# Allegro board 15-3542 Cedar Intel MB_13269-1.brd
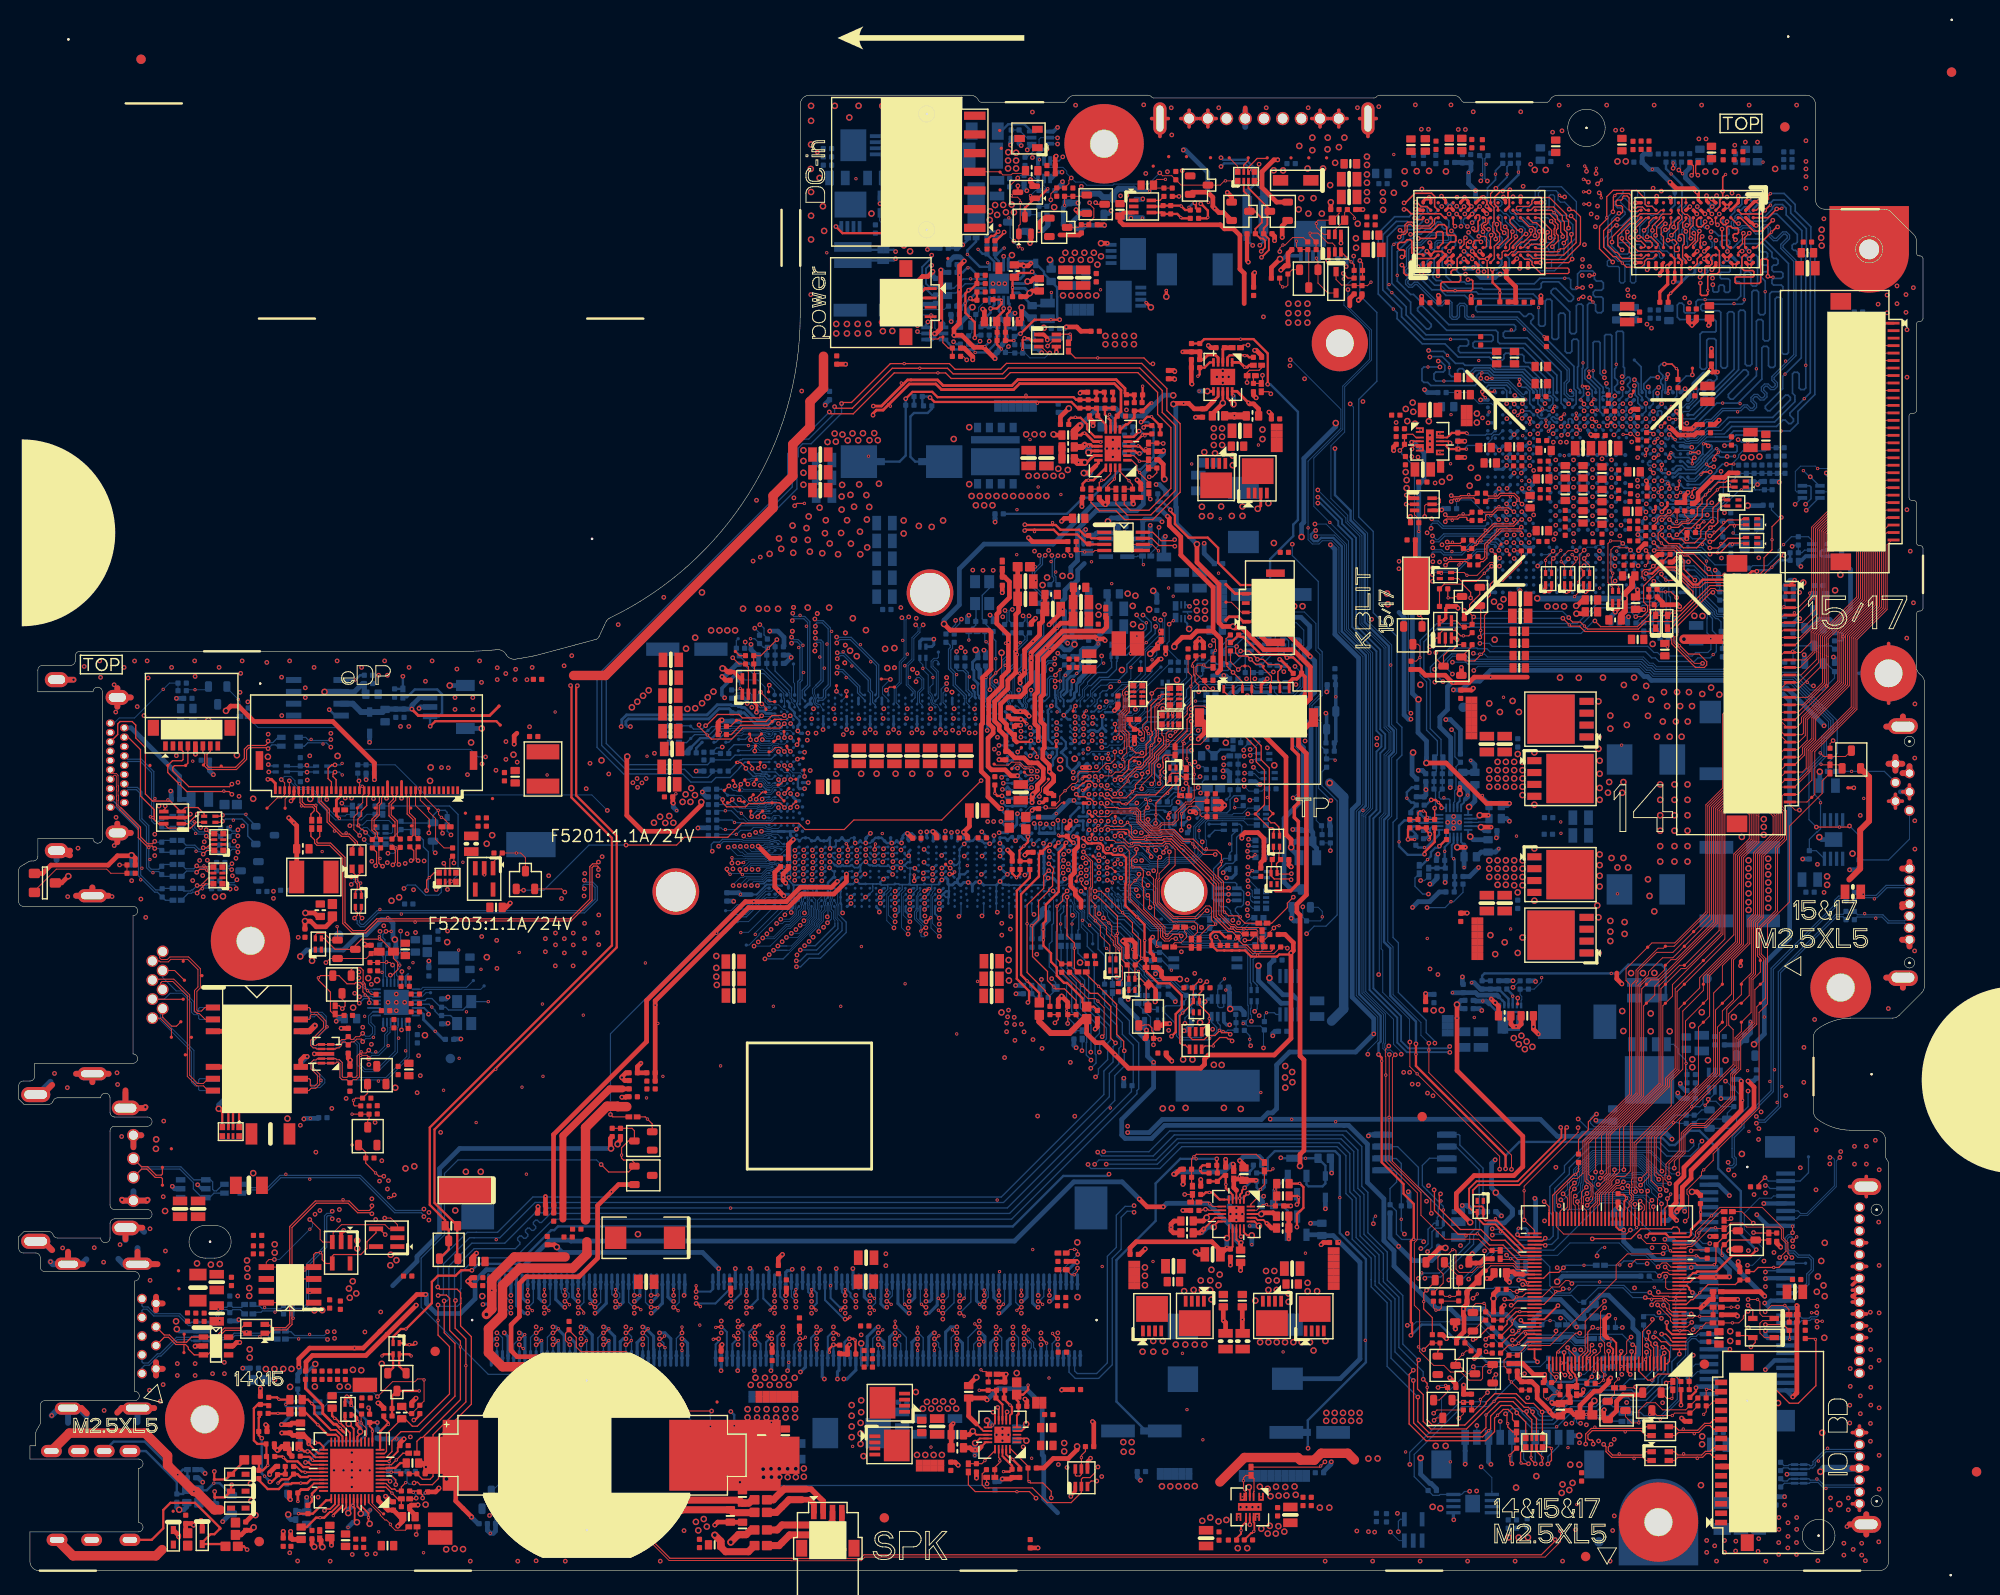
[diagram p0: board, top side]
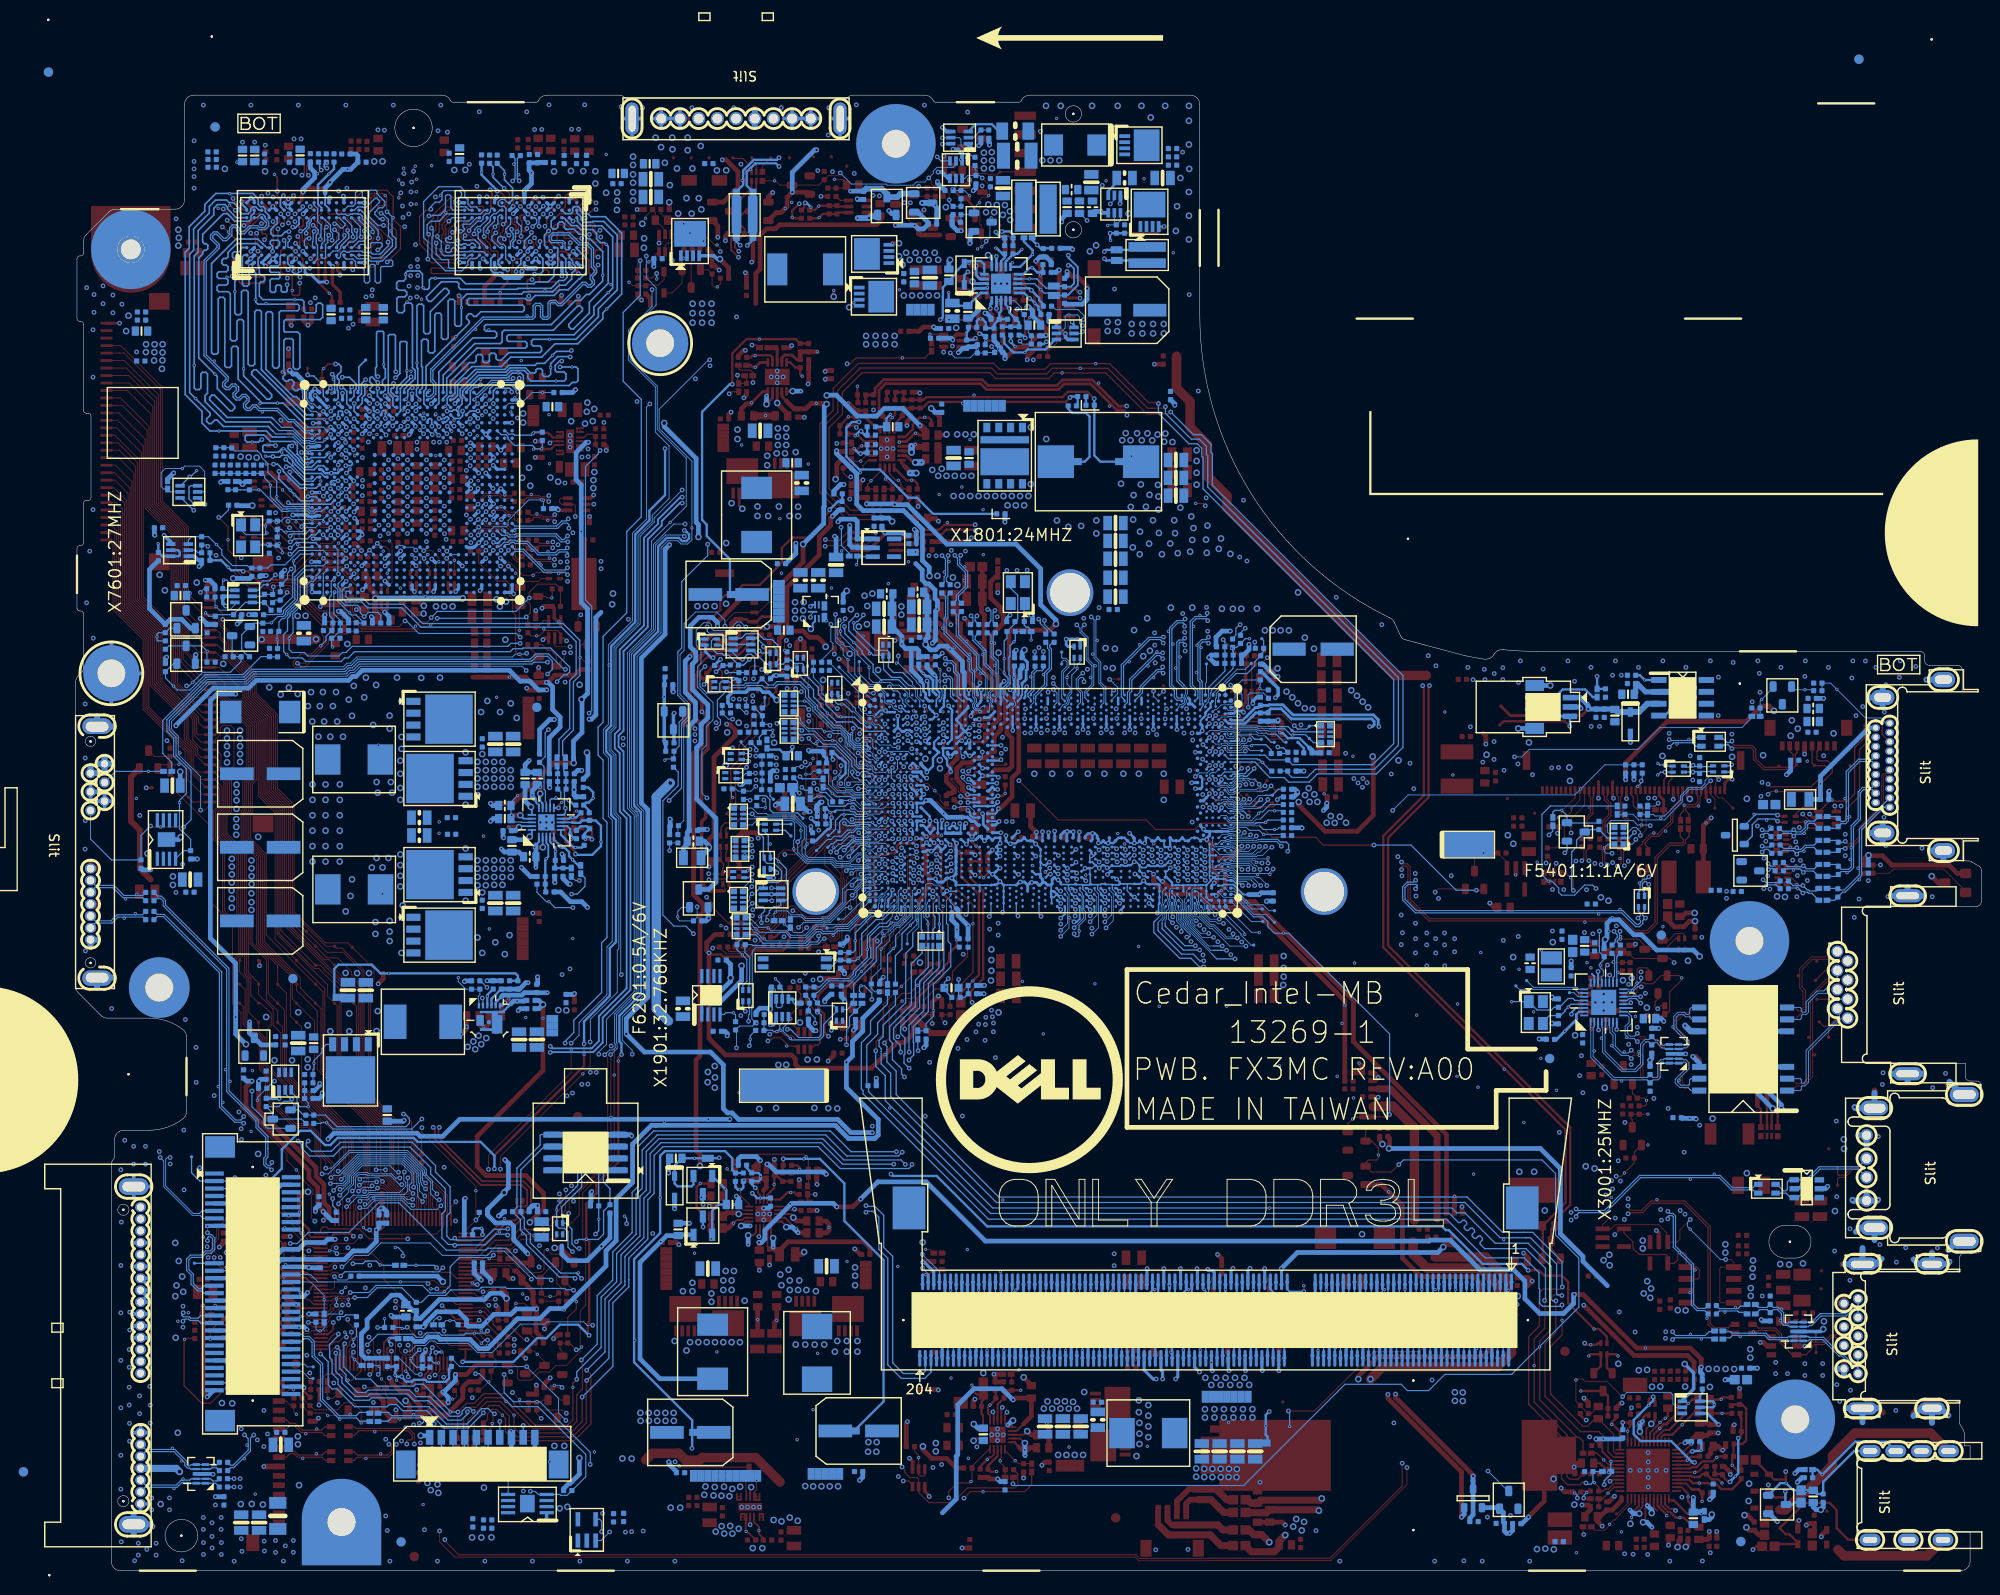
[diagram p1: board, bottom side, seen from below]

Outline 203.85 x 157.9 mm; copper layers: TOP, L2VCC, L3, L4, L5GND, BOTTOM. Coordinates in mm from the lower left corner of the outline.

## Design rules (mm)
constraint set DEFAULT: min track width 0.127, pair gap 0.102
net group AUDIO_8MIL: nets CPVEE V3D3_STB
net group CLK_PCI_KBC: nets CLK_PCI_KBC CLK_PCI_KBC_R
net group CLK_PCI_LPC: nets CLK_PCI_LPC CLK_PCI_LPC_R
net group CODEC_BITCLK_R: nets CODEC_BITCLK_R HDA_CODEC_BITCLK
net group CODEC_SDOUT_R: nets CODEC_SDOUT_R HDA_CODEC_SDOUT
net group CPU_RXN_C_DGPU_TXN0: nets CPU_RXN_C_DGPU_TXN0 DGPU_TXN_CPU_RXN0
net group CPU_RXN_C_DGPU_TXN1: nets CPU_RXN_C_DGPU_TXN1 DGPU_TXN_CPU_RXN1
net group CPU_RXN_C_DGPU_TXN2: nets CPU_RXN_C_DGPU_TXN2 DGPU_TXN_CPU_RXN2
net group CPU_RXN_C_DGPU_TXN3: nets CPU_RXN_C_DGPU_TXN3 DGPU_TXN_CPU_RXN3
net group CPU_RXP_C_DGPU_TXP0: nets CPU_RXP_C_DGPU_TXP0 DGPU_TXP_CPU_RXP0
net group CPU_RXP_C_DGPU_TXP1: nets CPU_RXP_C_DGPU_TXP1 DGPU_TXP_CPU_RXP1
net group CPU_RXP_C_DGPU_TXP2: nets CPU_RXP_C_DGPU_TXP2 DGPU_TXP_CPU_RXP2
net group CPU_RXP_C_DGPU_TXP3: nets CPU_RXP_C_DGPU_TXP3 DGPU_TXP_CPU_RXP3
net group DDC_CLK_HDMI: nets DDC_CLK_HDMI PCH_HDMI_CLK
net group DDC_DATA_HDMI: nets DDC_DATA_HDMI PCH_HDMI_DATA
net group DDR3_A_ODT10: nets M_A_DIMA_ODT0 M_A_DIMA_ODT1
net group DGPU_RXN_CPU_TXN0: nets DGPU_RXN_C_CPU_TXN0 DGPU_RXN_CPU_TXN0
net group DGPU_RXN_CPU_TXN1: nets DGPU_RXN_C_CPU_TXN1 DGPU_RXN_CPU_TXN1
net group DGPU_RXN_CPU_TXN2: nets DGPU_RXN_C_CPU_TXN2 DGPU_RXN_CPU_TXN2
net group DGPU_RXN_CPU_TXN3: nets DGPU_RXN_C_CPU_TXN3 DGPU_RXN_CPU_TXN3
net group DGPU_RXP_CPU_TXP0: nets DGPU_RXP_C_CPU_TXP0 DGPU_RXP_CPU_TXP0
net group DGPU_RXP_CPU_TXP1: nets DGPU_RXP_C_CPU_TXP1 DGPU_RXP_CPU_TXP1
net group DGPU_RXP_CPU_TXP2: nets DGPU_RXP_C_CPU_TXP2 DGPU_RXP_CPU_TXP2
net group DGPU_RXP_CPU_TXP3: nets DGPU_RXP_C_CPU_TXP3 DGPU_RXP_CPU_TXP3
net group EDP_AUX: nets EDP_AUX EDP_AUX_DP
net group EDP_AUX#: nets EDP_AUX# EDP_AUX_DN
net group EDP_TX0: nets EDP_TX0 EDP_TX0_DP
net group EDP_TX0#: nets EDP_TX0# EDP_TX0_DN
net group EDP_TX1: nets EDP_TX1 EDP_TX1_DP
net group EDP_TX1#: nets EDP_TX1# EDP_TX1_DN
net group FAN_TACH: nets FAN_TACH1 FAN_TACH1_C
net group GND: nets EC_AGND MIC_GND
net group H_CPU_SVIDCLK: nets H_CPU_SVIDCLK PWR_VCC_SCLK
net group H_CPU_SVIDDAT: nets H_CPU_SVIDDAT PWR_VCC_SDA
net group HDA_CODEC_SDIN0: nets HDA_CODEC_SDIN0 HDA_SDIN0
net group LAN_TXN_C_PCH_RXN4: nets LAN_TXN_C_PCH_RXN4 PCIE_PRX_LANTX_N4
net group LAN_TXP_C_PCH_RXP4: nets LAN_TXP_C_PCH_RXP4 PCIE_PRX_LANTX_P4
net group MG_CLK_PCIE_LAN: nets CLK_PCIE_LAN_N4 CLK_PCIE_LAN_P4
net group MG_VGA_CLK: nets CLK_PCIE_VGA CLK_PCIE_VGA#
net group PCH_SPI_DQ2: nets PCH_SPI_DQ2 SPI_WP#
net group PCH_SPI_DQ3: nets PCH_SPI_DQ3 SPI_HOLD#
net group PCIE_PTX_LANRX_N4: nets PCIE_PTX_LANRX_N4 PCIE_PTX_LANRX_N4_C
net group PCIE_PTX_LANRX_P4: nets PCIE_PTX_LANRX_P4 PCIE_PTX_LANRX_P4_C
net group PCIE_PTX_WLANRX_N3: nets PCIE_PTX_WLANRX_N3 PCIE_PTX_WLANRX_N3_C
net group PCIE_PTX_WLANRX_P3: nets PCIE_PTX_WLANRX_P3 PCIE_PTX_WLANRX_P3_C
net group PWR_VCC_FB: nets PWR_VCC_FB VCC_SENSE
net group PWR_VGA_CORE_RGND: nets PWR_VGA_CORE_RGND VGACORE_GND_SENSE_1
net group PWR_VGA_CORE_VSNS: nets PWR_VGA_CORE_VSNS VGACORE_VDD_SENSE_1
net group REF10M: nets KBC_VCORF PROC_OPI_COMP3
net group SATA_PRX_ODDTX_N2: nets SATA_PRX_ODDTX_N2 SATA_RXN2_R
net group SATA_PRX_ODDTX_P2: nets SATA_PRX_ODDTX_P2 SATA_RXP2_R
net group SATA_PTX_ODDRX_N2: nets SATA_PTX_ODDRX_N2 SATA_TXN2_R
net group SATA_PTX_ODDRX_P2: nets SATA_PTX_ODDRX_P2 SATA_TXP2_R
net group SMB_CHG_BAT-DIFF23: nets PWR_CHG_BAT_SCL PWR_CHG_BAT_SDA
net group SMB_XDP-DIFF: nets XDP_SMBCLK XDP_SMBDAT
net group T8-MW: nets VD_IN1 VD_IN1_C
net group USB2-DIFF: nets USB_PN2 USB_PP2
net group USB3_PTX_CRX_N0: nets USB3_PTX_CRX_N0 USB3_PTX_CRX_N0_R
net group USB3_PTX_CRX_P0: nets USB3_PTX_CRX_P0 USB3_PTX_CRX_P0_R
net group USB30_RX0-DIFF: nets USB3_PRX_CTX_N0 USB3_PRX_CTX_P0
net group USB_PN0: nets USB_PN0 USB_PN0_C
net group USB_PN7: nets USB_PN7 USB_PN7_IOBD1
net group USB_PP0: nets USB_PP0 USB_PP0_C
net group USB_PP7: nets USB_PP7 USB_PP7_IOBD1
net group AUDIO_BEEP: nets AUD_HP1_JACK_L AUD_HP1_JACK_L1 AUD_HP1_JACK_R AUD_HP1_JACK_R1 AUD_PC_BEEP AUD_PC_BEEP_C AUD_PORTA_L_R_B AUD_PORTA_R_R_B AUD_SENSE AUD_SENSE_A AUD_VREF CBN CBP HDA_SPKR HDA_SPKR_R JACK_PLUG JACK_PLUG_DET KBC_BEEP KBC_BEEP_R LINE1-L_C LINE1-L_R LINE1_L LINE1_R LINE1_VREFO_L LINE1_VREFO_R MIC2_VREFO SLEEVE_CTRL
net group AUDIO_BEEP1: nets AUD_SPK_L+ AUD_SPK_L+_C AUD_SPK_L- AUD_SPK_L-_C AUD_SPK_R+ AUD_SPK_R+_C AUD_SPK_R- AUD_SPK_R-_C
net group AUDIO_SLEEVE: nets RING2
net group CARD_12MIL: nets RSET
net group CFG-MW: nets CFG0 CFG1 CFG2 CFG3 CFG4 CFG5 CFG6 CFG7 CFG8 CFG9 CFG10 CFG11 CFG12 CFG13 CFG14 CFG15 CFG16 CFG17 CFG18 CFG19
net group CL-MW: nets TP_CL_CLK TP_CL_DATA TP_CL_RST#
net group CLK-MW: nets LANXIN LANXOUT PEXTSTCLK_OUT PEXTSTCLK_OUT# SUS_CLK SUS_CLK_PCH SUSCLK_KBC VIDEO_CLK_XTAL_SS
net group COMP_20: nets CFG_RCOMP EDP_COMP PCH_OPIRCOMP PCIE_RCOMP PROC_OPI_COMP SATA_IREF SATA_RCOMP SM_RCOMP_0 SM_RCOMP_1 SM_RCOMP_2 TD_IREF USB_COMP XCLK_BIASREF
net group CPU-MW: nets H_PECI H_PROCHOT# H_PROCHOT#_EC H_PROCHOT#_R PECI PQ4008_6 PQ4405_3 PQ4406_D PROCHOT_EC VGA_CORE_VID
net group DDR3_A_CMD: nets M_A_A0 M_A_A1 M_A_A2 M_A_A3 M_A_A4 M_A_A5 M_A_A6 M_A_A7 M_A_A8 M_A_A9 M_A_A10 M_A_A11 M_A_A12 M_A_A13 M_A_A14 M_A_A15 M_A_BS0 M_A_BS1 M_A_BS2 M_A_CAS# M_A_RAS# M_A_WE#
net group EC_SPI_CLK_C: nets EC_SPI_CLK_C PCH_SPI_CLK SPI_CLK_R
net group EC_SPI_CS#_C: nets EC_SPI_CS#_C PCH_SPI_CS0# SPI_CS0#_R
net group EC_SPI_DI_C: nets EC_SPI_DI_C PCH_SPI_SI SPI_SI_R
net group EC_SPI_DO_C: nets EC_SPI_DO_C PCH_SPI_SO SPI_SO_R
net group FBA_VREF: nets FBA_VREF_0 FBA_VREF_1 PWR_VRAM_PWR_ILIM
net group H_CPU_SVIDALRT#: nets H_CPU_SVIDALRT# PWR_VCC_ALERT# VR_SVID_ALERT#
net group HDA_CODEC_RST#: nets HDA_CODEC_RST#
net group HDA_CODEC_SYNC: nets HDA_CODEC_SYNC
net group HDMI_CLK: nets HDMI_CLK HDMI_CLK_R HDMI_CLK_R_C
net group HDMI_CLK#: nets HDMI_CLK# HDMI_CLK#_R HDMI_CLK#_R_C
net group HDMI_DATA0: nets HDMI_DATA0 HDMI_DATA0_R HDMI_DATA0_R_C
net group HDMI_DATA0#: nets HDMI_DATA0# HDMI_DATA0#_R HDMI_DATA0#_R_C
net group HDMI_DATA1: nets HDMI_DATA1 HDMI_DATA1_R HDMI_DATA1_R_C
net group HDMI_DATA1#: nets HDMI_DATA1# HDMI_DATA1#_R HDMI_DATA1#_R_C
net group HDMI_DATA2: nets HDMI_DATA2 HDMI_DATA2_R HDMI_DATA2_R_C
net group HDMI_DATA2#: nets HDMI_DATA2# HDMI_DATA2#_R HDMI_DATA2#_R_C
net group JTAG: nets PCH_JTAG_TCK PCH_JTAG_TDI PCH_JTAG_TDO PCH_JTAG_TMS PCH_JTAG_TRST#
net group KB: nets KB_BL_CTRL KCOL0 KCOL1 KCOL2 KCOL3 KCOL4 KCOL5 KCOL6 KCOL7 KCOL8 KCOL9 KCOL10 KCOL11 KCOL12 KCOL13 KCOL14 KCOL15 KCOL16 KROW0 KROW1 KROW2 KROW3 KROW4 KROW5 KROW6 KROW7
net group LAN0_MDO1-DIFF: nets MDO1+
net group LCD_BKLT-MW: nets BKLT_CTRL EC_BRIGHTNESS EDP_BKLT_CTRL EDP_BRIGHTNESS L_BKLT_CTRL LCD_BRIGHTNESS
net group LED: nets AMBER_LED_BAT BAT_AMBER BAT_WHITE BATT_WHITE_LED# BATT_WHITE_LED_R# CAP_LED CAP_LED# CAP_LED_Q CAP_LED_R# CHG_AMBER_LED# CHG_AMBER_LED_R# SATA_LED# WHITE_LED_BAT
net group LPC-MWS: nets INT_SERIRQ LPC_AD0 LPC_AD1 LPC_AD2 LPC_AD3 LPC_FRAME# LPC_FRAME#_DEBUG LPC_LAD0_PCH LPC_LAD0_R LPC_LAD1_PCH LPC_LAD1_R LPC_LAD2_PCH LPC_LAD2_R LPC_LAD3_PCH LPC_LAD3_R LPC_LFRAME#_PCH
net group OTHER_4MIL: nets 1D05V_VGA_S0_DISCHG AC_IN# AC_IN_KBC# AC_PRESENT AD+_G_1 AD_IA AD_IA_HW AD_IA_HW2 ALERT# AMP_MUTE# BAT_IN# BATLOW# BLON_OUT BLON_OUT_C BLUETOOTH_EN BOARD_ID1 BOARD_ID2 BOARD_ID3 BOOST_MON_1 BUFRST# CAMERA_PWR_EN CARD_PWR_EN CARD_WLAN_OUT# CARD_WPAN_OUT# CEDAR/JANUS_ID CLK_PCIE_WLAN_REQ3# COLOR_ENGINE COMBO-GPI DBC_EN DBC_EN_R DC_TEST_A3_B3 DC_TEST_A61_B61 DC_TEST_AY2_AW2 DC_TEST_AY3_AW3 DC_TEST_AY61_AW61 DC_TEST_AY62_AW62 DC_TEST_B62_B63 DC_TEST_C1_C2 DDPC_CTRLDATA DGPU_PWR_EN# DSWODVREN E51_TXD EAPD# EC_SCI# EC_SMI# EC_SWI# ECRST# ECSCI#_KBC ECSMI#_KBC ECSWI#_KBC EDP_HPD EDP_HPD_CONN EDP_SPARE FB_VREF FBA_DEBUG0 FBA_DEBUG1 H_CATERR# H_RCIN# H_THERMTRIP# H_THERMTRIP_EN HDD_DEVSLP HDMI_HPD_B HDMI_HPD_E HDMI_PCH_DET HPD_HDMI_CON HSIOPC HSIOPC_R HVM_CLK HVM_CLK# IFPAB_IOVDD IFPAB_PLLVDD IFPC_IOVDD IFPC_PLLVDD IFPD_IOVDD IFPD_PLLVDD IFPEF_IOVDD IFPEF_PLLVDD INT_TP# INT_TP#_GPIO8 INT_TP#_GPIO55 ISOLATE# JDREF KB_DET# KB_LED_BL_DET KB_LED_DET_C KBC_ON#_GATE KBC_ON#_GATE_L KBC_PWRBTN# L_BKLT_EN L_BKLT_EN_EC LCD_TST LCD_TST_C LCD_TST_EN LCDVDD_EN LED0 LED1 LED2 LID_CLOSE# LPSS_GSPI0_MOSI_BBS0_R LPSS_SDIO_D0_CMNHDR MCP_GPIO11 MCP_GPIO12 MCP_GPIO13 MCP_GPIO14 MCP_GPIO15 MCP_GPIO26 MCP_GPIO27 MCP_GPIO28 MCP_GPIO36 MCP_GPIO44 MCP_GPIO56 MCP_GPIO57 MCP_GPIO58 MCP_GPIO73 MCP_GPIO76 MCP_R MCP_TESTLOW1 MCP_TESTLOW2 MCP_TESTLOW3 MCP_TESTLOW4 ME_UNLOCK MODEL_ID_DET MUTE_CTRL N12P_JTAG_TCK N12P_JTAG_TDI N12P_JTAG_TDO N12P_JTAG_TMS N12P_JTAG_TRST N12P_XTAL_OUTBUFF PANEL_SIZE_ID PANEL_SIZE_ID_CONN PCB_VER_AD PCH_INTVRMEN PCH_THERMTRIP PCH_WAKE# PCI_PME# PD4403_A PD4403_K PEX_TERMP PIRQA# PIRQB# PIRQC# PIRQD# PLT_RST# PLT_RST#_EC PM_CLKRUN# PM_CLKRUN#_EC PM_PWRBTN# PM_SLP_A# PM_SLP_SUS# PQ3808D PQ3808G PQ4203_5 PQ4405_2 PQ4405_5 PQ4405_6 PQ4406_G PQ4408_C PQ4408_E PR4601_1 PS_ID_R PSID_EC PSL_IN1# PSL_IN2# PSL_OUT# PU5102_PG PWR_5V_VCLK PWR_CHG_ACOK PWR_CHG_AD_OFF PWR_CHG_AD_OFF_R PWR_VRAM_PWR_EN Q402_1 Q7601_G RSVDA51 RSVDAU63 RSVDAV63 RSVDB51 RSVDC62 RSVDC63 RSVDL60 RSVDN59 RSVDN61 RSVDP60 RSVDP61 RTC_DET# SA0_DIMA SA1_DIMA SM_INTRUDER# TESTMODE TP_DC_TEST_A4 TP_DC_TEST_A60 TP_DC_TEST_A62 TP_DC_TEST_AV1 TP_DC_TEST_AW1 TP_DC_TEST_AW63 TP_DC_TEST_AY60 TP_DC_TEST_B2 TP_HDA_DOCK_EN# TP_M_A_DIMA_ODT0 TP_RESET TP_RS TP_V1.05S_APLLOPI TP_V1.05S_AXCK_DCB TP_V1.05S_SSCF100 TP_V1.05S_SSCFF TP_VCCAPLLOPI_VAL TP_VCCIO_OUT USB_OC#0_1 USB_OC#2_3 USB_OC#4_5 USB_OC#6_7 VGA_CORE_DISCHG WIFI_RF_EN WLAN_PLT_RST#
net group PLATFORM: nets 1D05V_VGA_EN 1D05V_VTT_PWRGD 1D35V_ENABLE 1D35V_ENABLE_RC 1D35V_VGA_EN 1D35V_VTT_PWRGD 3V5V_S0_ON 3V_5V_EN 3V_5V_POK 3V_5V_POK# 3V_5V_POK_C AC_IN#_G ALL_SYS_PWRGD CLK_LAN_REQ4#_R CLK_LAN_REQ#_EN CLK_PCIE_LAN_REQ4# CLK_PCIE_REQ# DDR3_DRAMRST# DDR_PG_CTRL DDR_PG_CTRL_R DDR_VTT_PG_CTRL DDR_VTT_PG_CTRL_R DGPU_HOLD_RST# DGPU_PWR_EN DGPU_PWROK DGPU_PWROK_KBC DS3_PWRCTL EDP_VDD_EN GC6_FB_EN GC6_FB_EN_GPU GC6_FB_EN_KBC GC6_FB_EN_MCP GPIO5_GC6_PWR_EN GPIO5_GC6_PWR_EN# GPIO5_GC6_PWR_EN_GPU GPIO5_GC6_PWR_EN_R# GPIO9_ALERT GPIO10_FBVREF GPU_CLKREQ# GPU_EVENT# GPU_EVENT_GPU# GPU_EVENT_MCP# GPU_PEX_RST# GPU_PEX_RST_D# GPU_PEX_RST_HOLD GPU_PEX_RST_HOLD_GPU# H_CPUPWRGD H_VCCST_PWRGD H_VR_ENABLE IMVP_PWRGD IMVP_PWRGD_R INT_TP#_GPIO46 INT_TP#_KBC KBC_DPWROK KBC_PWRBTN#_C LAN_ENABLE_R_C MPWROK OVERT# OVERT_GPU# PCH_DPWROK PCH_PWROK PCH_SLP_S0# PCH_SLP_WLAN# PCI_PLTRST# PCIE_WAKE# PEG_CLKREQ# PLT_RST#_DEBUG PLT_RST#_LAN PM_LAN_ENABLE PM_LAN_ENABLE_R PM_PCH_PWROK PM_RSMRST# PM_SLP_LAN# PM_SLP_S3# PM_SLP_S4# PM_SLP_S5# PM_SUS_STAT# PM_SUSACK# PM_SUSACK#_R PM_SUSWARN# PM_SUSWARN#_R PS_S3CNTRL PU4401_6 PWR_1D5V_EN PWR_1D35V_EN PWR_3D3V_EN2 PWR_5V_EN1 PWR_5V_EN1_R PWR_LEVEL PWR_VCC_EN PWR_VCC_POK ROM_CS# ROM_SCLK ROM_SI ROM_SO RSMRST#_KBC RTC_RST# RTCRST_ON S5_ENABLE SATA_ODD_DA# SATA_ODD_DA#_C SATA_ODD_PRSNT# SATA_ODD_PWRGT SM_DRAMRST# SRTC_RST# STRAP0 STRAP1 STRAP2 STRAP3 STRAP4 STRAP_REF0_GND_N9 SYS_PEX_RST_MON# SYS_PEX_RST_MON_GPU# SYS_PWROK TOUCH_PANEL_INTR# TOUCH_PANEL_INTR_KBC# TP_LID_CLOSE# TP_LID_CLOSE#_KBC TP_ON# TP_ON#_GATE USB_PN3 USB_PP3 USB_PWR_EN# VGA_CORE_PSI VIDEO_THERM_OVERT#
net group POWER_10M: nets 3V5V_CT1 3V5V_CT2 +3.3A_DSW_PRTCSUS +PCH_VCCDSW +V1.05A_SUS_PCH +V1.05A_USB2SUS +V1.05A_VCCUSB3SUS +V3.3A_1.5A_HDA +V3.3A_DSW_P +V3.3S_1.8S_LPSS_SDIO +V3.3S_PCORE +VCCRTCEXT +VCHGR_R AD+_G_2 BOOST_MODE# BOOST_MON DCBATOUT_R EC_VBKUP FAN1_DAC_1 FB_CLAM FB_CLAMP_MON_S FBA_ZQ0 FBA_ZQ1 FBA_ZQ2 FBA_ZQ3 ISUM_R_R LDO1_CAP LDO2_CAP LDO3_CAP MIC_CAP PCH_VCCDSW_R PHASE_R_R PQ4008_2 PU4401_4 PU4401_5 PWR_1D05V_CCM PWR_1D05V_TRIP PWR_1D35V_VDDQS PWR_1D35V_VTTREF PWR_VCC_COMP PWR_VCC_COMP_RC PWR_VCC_ISUMN PWR_VCC_ISUMP PWR_VCC_NTC PWR_VCC_NTC_R PWR_VCC_PRGM1 PWR_VCC_PRGM2 PWR_VCC_VRHOT# PWR_VGA_CORE_EN PWR_VGA_CORE_PSI PWR_VGA_CORE_REFIN PWR_VGA_CORE_VID PWR_VGA_CORE_VREF Q6204_G REFIN_VREF VTT_CT_3VC_1 VTT_CT_105VC_2 XDP_PWR_DEBUG
net group POWER_10M_POWER: nets 3V_FEEDBACK 15V_PWR AD_OFF_L BOOST_10V BST15V_1 BST15V_2 ISUM_R_C PHASE1G PQ3809_D PWR_1D05V_PWR PWR_1D35V_MODE PWR_1D35V_REFIN PWR_1D35V_TRIP PWR_1D35V_VREF PWR_3D3V_CS2 PWR_3D3V_FB2 PWR_3D3V_FB2_R PWR_5V_CS1 PWR_5V_FB1 PWR_5V_FB1_R PWR_CHG_ACDET PWR_CHG_BTST_R PWR_CHG_CMPIN PWR_CHG_CMPIN_R PWR_CHG_CMPIN_RR PWR_CHG_CMPOUT PWR_CHG_IFAULT PWR_CHG_ILIM PWR_CHG_IOUT PWR_CHG_REGN PWR_CHG_VCC PWR_VCC_FB_RC PWR_VCC_IMON PWR_VGA_CORE_REFADJ PWR_VGA_CORE_SS PWR_VGA_CORE_TON PWR_VGA_CORE_TON_1
net group POWER_15M: nets Q6203_S
net group POWER_20M: nets 3D3V_AUX_KBC_VCC 3D3V_AUX_S5 5V_HDMI_S0 15V_S5 +5V_AVDD +RTC_VCC +V1.05A_AOSCSUS +V1.05S_AIDLE +V1.05S_APLLOPI +V1.05S_ASATA3PLL +V1.05S_AUSB3PLL +V1.05S_AXCK_DCB +V1.05S_AXCK_LCPLL +V1.05S_SSCF100 +V1.05S_SSCFF +V3.3A_PSUS +V_SM_VREF_CNT +V_VREF_PATH1 +V_VREF_PATH3 +VCCIOA_OUT DC_IN_D DDR_WR_VREF01 EC_VTT MCT0 MCT1 MCT2 MCT3 PR4605_2 PWR_1D05V_BOOT PWR_1D05V_EN PWR_1D05V_FB PWR_1D05V_PWRGD PWR_1D35V_VBST PWR_3D3V_VBST2 PWR_3D3V_VBST2_1 PWR_5V_VBST1 PWR_5V_VBST1_1 PWR_5V_VO1 PWR_CHG_BTST PWR_DEBUG RTC_PWR TPAN_VDD VBAT VRAM_PWR_BS VRAM_PWR_BS_R VRAM_PWR_BYP VRAM_PWR_FB VRAM_PWR_FBH VRAM_PWR_LDO
net group POWER_20M_POWER: nets 3D3V_PWR_2 5V_PWR_2 +5V_KB_BL +5V_MINI_DEBUG KB_BL_CTRL# PWR_3D3V_SNUB PWR_5V_SNUB PWR_VGA_CORE_BOOT1 PWR_VGA_CORE_BOOT1_1 PWR_VGA_CORE_BOOT2 PWR_VGA_CORE_BOOT2_1
net group POWER_25M: nets PQ3802_1 PS_ID PSID_DISABLE#_R_C
net group POWER_40M: nets DIS_1D35V_VGA_S0 FAN_VCC1 FB_CAL_PD_VDDQ FB_CAL_PU_GND FB_CAL_TERM_GND LOM_TCT M_A_B_DIMM_ODT PWR_1D05V_BOOT_R PWR_VCC_BOOT PWR_VCC_BOOT_RC
net group POWER_160M: nets RT8812_PVCC
net group SATA3_PRX_HDDTX_N0: nets SATA3_PRX_HDDTX_N0
net group SATA3_PRX_HDDTX_P0: nets SATA3_PRX_HDDTX_P0
net group SATA3_PTX_HDDRX_N0: nets SATA3_PTX_HDDRX_N0
net group SATA3_PTX_HDDRX_P0: nets SATA3_PTX_HDDRX_P0
net group SENSE_VCORE-DIFF: nets VSS_SENSE
net group THERM_10M: nets FON# VD1_EN# VD_OUT1#
net group THERM_SHUTDOWN: nets OVER_CURRENT_P8# P_H_S# PURE_HW_SHUTDOWN# T_CRIT# THERM_SYS_SHDN#
net group USB_CAMERA: nets USB_CAMERA USB_CAMERA_EDP USB_PP4 USB_PP4_CAM USB_PP4_EDP
net group USB_CAMERA#: nets USB_CAMERA# USB_CAMERA_EDP# USB_PN4 USB_PN4_CAM# USB_PN4_EDP
net group USB_PN1: nets USB_PN1
net group USB_PP1: nets USB_PP1
net group VRAM_CMD-MW: nets FBA_CMD0 FBA_CMD1 FBA_CMD2 FBA_CMD3 FBA_CMD4 FBA_CMD5 FBA_CMD6 FBA_CMD7 FBA_CMD8 FBA_CMD9 FBA_CMD10 FBA_CMD11 FBA_CMD12 FBA_CMD13 FBA_CMD14 FBA_CMD15 FBA_CMD16 FBA_CMD17 FBA_CMD18 FBA_CMD19 FBA_CMD20 FBA_CMD21 FBA_CMD22 FBA_CMD23 FBA_CMD24 FBA_CMD25 FBA_CMD26 FBA_CMD27 FBA_CMD28 FBA_CMD29 FBA_CMD30 FBA_CMD31
net group VRAM_DBI-MW: nets FBA_DQM0 FBA_DQM1 FBA_DQM2 FBA_DQM3 FBA_DQM4 FBA_DQM5 FBA_DQM6 FBA_DQM7
net group VRAM_DQ-MW: nets FBA_D0 FBA_D1 FBA_D2 FBA_D3 FBA_D4 FBA_D5 FBA_D6 FBA_D7 FBA_D8 FBA_D9 FBA_D10 FBA_D11 FBA_D12 FBA_D13 FBA_D14 FBA_D15 FBA_D16 FBA_D17 FBA_D18 FBA_D19 FBA_D20 FBA_D21 FBA_D22 FBA_D23 FBA_D24 FBA_D25 FBA_D26 FBA_D27 FBA_D28 FBA_D29 FBA_D30 FBA_D31 FBA_D32 FBA_D33 FBA_D34 FBA_D35 FBA_D36 FBA_D37 FBA_D38 FBA_D39 FBA_D40 FBA_D41 FBA_D42 FBA_D43 FBA_D44 FBA_D45 FBA_D46 FBA_D47 FBA_D48 FBA_D49 FBA_D50 FBA_D51 FBA_D52 FBA_D53 FBA_D54 FBA_D55 FBA_D56 FBA_D57 FBA_D58 FBA_D59 FBA_D60 FBA_D61 FBA_D62 FBA_D63
net group WLAN-MW: nets BT_ACT DEBUG E51_RX E51_TX WLAN_ACT
net group XDP-MW: nets BP_PWRGD_RST# VCCST_PWRGD_XDP XDP_DBRESET# XDP_PRDY# XDP_PREQ# XDP_RST XDP_SYS_PWROK XDP_TCK_JTAGX XDP_TDI XDP_TDO XDP_TMS XDP_TRST#
net group XDP_BPM-MW: nets XDP_BPM0 XDP_BPM1 XDP_BPM2 XDP_BPM3 XDP_BPM4 XDP_BPM5 XDP_BPM6 XDP_BPM7
net group XDP_TCLK-MW: nets XDP_TCLK
net group XTAL-MW: nets 27MHZ_OUT_R RTC_X1 RTC_X2 XTAL24_IN XTAL24_IN_R XTAL24_OUT

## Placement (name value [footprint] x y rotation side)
AFTP2501  AFTE14P-GP  [AFTE14P-75]  74.7 18.05 270 top
AFTP2502  AFTE14P-GP  [AFTE14P-75]  47.54 6.66 0 top
AFTP2801  AFTE14P-GP  [AFTE14P-75]  51.38 92.52 0 top
AFTP2802  AFTE14P-GP  [AFTE14P-75]  51.51 90.49 0 top
AFTP2803  AFTE14P-GP  [AFTE14P-75]  53.28 89.62 180 top
AFTP2901  AFTE14P-GP  [AFTE14P-75]  81.63 2.99 0 top
AFTP2902  AFTE14P-GP  [AFTE14P-75]  81.66 4.89 0 top
AFTP2903  AFTE14P-GP  [AFTE14P-75]  81.86 8.73 0 top
AFTP2904  AFTE14P-GP  [AFTE14P-75]  81.63 6.82 0 top
AFTP2906  AFTE14P-GP  [AFTE14P-75]  21.54 4.51 0 top
AFTP2907  AFTE14P-GP  [AFTE14P-75]  20.92 9.76 0 top
AFTP2908  AFTE14P-GP  [AFTE14P-75]  16.52 6.37 0 top
AFTP2909  AFTE14P-GP  [AFTE14P-75]  21 7.84 0 top
AFTP3101  AFTE14P-GP  [AFTE14P-75]  17.6 61.16 90 top
AFTP3102  AFTE14P-GP  [AFTE14P-75]  17.35 58.74 90 top
AFTP3103  AFTE14P-GP  [AFTE14P-75]  17.82 55.21 90 top
AFTP3104  AFTE14P-GP  [AFTE14P-75]  18.48 57.08 90 top
AFTP3105  AFTE14P-GP  [AFTE14P-75]  17.6 65.22 90 top
AFTP3106  AFTE14P-GP  [AFTE14P-75]  17.73 63.19 90 top
AFTP3107  AFTE14P-GP  [AFTE14P-75]  16.33 57.09 90 top
AFTP3108  AFTE14P-GP  [AFTE14P-75]  19.6 63.68 90 top
AFTP3801  AFTE14P-GP  [AFTE14P-75]  104.98 147.77 0 top
AFTP3802  AFTE14P-GP  [AFTE14P-75]  104.98 149.67 90 top
AFTP3803  AFTE14P-GP  [AFTE14P-75]  104.94 154.12 0 top
AFTP3805  AFTE14P-GP  [AFTE14P-75]  104.98 143.96 0 top
AFTP3806  AFTE14P-GP  [AFTE14P-75]  105.1 152.21 0 top
AFTP3901  AFTE14P-GP  [AFTE14P-75]  127.48 151.21 0 top
AFTP3902  AFTE14P-GP  [AFTE14P-75]  129.49 151.2 0 top
AFTP3903  AFTE14P-GP  [AFTE14P-75]  131.52 151.2 0 top
AFTP3904  AFTE14P-GP  [AFTE14P-75]  133.55 151.2 0 top
AFTP3905  AFTE14P-GP  [AFTE14P-75]  136.09 151.2 0 top
AFTP3906  AFTE14P-GP  [AFTE14P-75]  123.01 151.33 0 top
AFTP3907  AFTE14P-GP  [AFTE14P-75]  139.9 151.2 0 top
AFTP3908  AFTE14P-GP  [AFTE14P-75]  138 151.2 0 top
AFTP3909  AFTE14P-GP  [AFTE14P-75]  121.36 150.31 0 top
AFTP3910  AFTE14P-GP  [AFTE14P-75]  124.91 151.33 0 top
AFTP5201  AFTE14P-GP  [AFTE14P-75]  43.84 81.57 0 top
AFTP5202  AFTE14P-GP  [AFTE14P-75]  47.79 81.06 0 top
AFTP5203  AFTE14P-GP  [AFTE14P-75]  36.28 79.71 0 top
AFTP5204  AFTE14P-GP  [AFTE14P-75]  50.68 82.63 0 top
AFTP5205  AFTE14P-GP  [AFTE14P-75]  36.22 81.62 0 top
AFTP5206  AFTE14P-GP  [AFTE14P-75]  41.94 81.62 0 top
AFTP5207  AFTE14P-GP  [AFTE14P-75]  43.91 79.67 0 top
AFTP5208  AFTE14P-GP  [AFTE14P-75]  42.01 79.71 0 top
AFTP5209  AFTE14P-GP  [AFTE14P-75]  28.5 81.59 90 top
AFTP5210  AFTE14P-GP  [AFTE14P-75]  40.1 79.71 0 top
AFTP5211  AFTE14P-GP  [AFTE14P-75]  38.2 79.71 0 top
AFTP5212  AFTE14P-GP  [AFTE14P-75]  38.13 81.62 0 top
AFTP5213  AFTE14P-GP  [AFTE14P-75]  40.03 81.62 0 top
AFTP5214  AFTE14P-GP  [AFTE14P-75]  26.57 81.6 0 top
AFTP5222  AFTE14P-GP  [AFTE14P-75]  15.95 86.17 0 top
AFTP5225  AFTE14P-GP  [AFTE14P-75]  19.76 86.22 0 top
AFTP5226  AFTE14P-GP  [AFTE14P-75]  21.66 86.1 0 top
AFTP5227  AFTE14P-GP  [AFTE14P-75]  14.04 86.17 0 top
AFTP5228  AFTE14P-GP  [AFTE14P-75]  17.85 86.17 0 top
AFTP6201  AFTE14P-GP  [AFTE14P-75]  184.27 65.3 0 top
AFTP6202  AFTE14P-GP  [AFTE14P-75]  191.8 82.76 0 top
AFTP6203  AFTE14P-GP  [AFTE14P-75]  176.14 64.79 0 top
AFTP6204  AFTE14P-GP  [AFTE14P-75]  15.38 43.16 0 top
AFTP6205  AFTE14P-GP  [AFTE14P-75]  16.33 45.15 0 top
AFTP6206  AFTE14P-GP  [AFTE14P-75]  180.2 65.3 0 top
AFTP6207  AFTE14P-GP  [AFTE14P-75]  176.14 62.76 0 top
AFTP6208  AFTE14P-GP  [AFTE14P-75]  178.17 62.76 0 top
AFTP6209  AFTE14P-GP  [AFTE14P-75]  15.38 41.25 0 top
AFTP6210  AFTE14P-GP  [AFTE14P-75]  17.14 30.17 0 top
AFTP6211  AFTE14P-GP  [AFTE14P-75]  17.7 25.31 0 top
AFTP6212  AFTE14P-GP  [AFTE14P-75]  17.68 23.34 0 top
AFTP6213  AFTE14P-GP  [AFTE14P-75]  180.2 60.73 0 top
AFTP6214  AFTE14P-GP  [AFTE14P-75]  184.27 60.73 0 top
AFTP6215  AFTE14P-GP  [AFTE14P-75]  182.24 62.76 0 top
AFTP6216  AFTE14P-GP  [AFTE14P-75]  178.17 66.82 0 top
AFTP6217  AFTE14P-GP  [AFTE14P-75]  17.09 32.1 0 top
AFTP6218  AFTE14P-GP  [AFTE14P-75]  184.27 58.69 0 top
AFTP6219  AFTE14P-GP  [AFTE14P-75]  179.17 68.39 0 top
AFTP6220  AFTE14P-GP  [AFTE14P-75]  176.14 66.82 0 top
AFTP6221  AFTE14P-GP  [AFTE14P-75]  186.3 60.73 0 top
AFTP6222  AFTE14P-GP  [AFTE14P-75]  186.3 62.76 0 top
AFTP6223  AFTE14P-GP  [AFTE14P-75]  180.2 62.76 0 top
AFTP6224  AFTE14P-GP  [AFTE14P-75]  180.2 58.69 0 top
AFTP6225  AFTE14P-GP  [AFTE14P-75]  174.11 60.73 0 top
AFTP6226  AFTE14P-GP  [AFTE14P-75]  176.14 60.73 0 top
AFTP6227  AFTE14P-GP  [AFTE14P-75]  184.27 62.76 0 top
AFTP6228  AFTE14P-GP  [AFTE14P-75]  182.24 60.73 0 top
AFTP6229  AFTE14P-GP  [AFTE14P-75]  174.11 62.76 0 top
AFTP6230  AFTE14P-GP  [AFTE14P-75]  186.3 65.3 0 top
AFTP6231  AFTE14P-GP  [AFTE14P-75]  178.17 60.73 0 top
AFTP6232  AFTE14P-GP  [AFTE14P-75]  174.25 66.72 0 top
AFTP6233  AFTE14P-GP  [AFTE14P-75]  178.17 64.79 0 top
AFTP6234  AFTE14P-GP  [AFTE14P-75]  182.24 58.69 0 top
AFTP6235  AFTE14P-GP  [AFTE14P-75]  170.94 63.96 0 top
AFTP6236  AFTE14P-GP  [AFTE14P-75]  134.18 81.01 0 top
AFTP6237  AFTE14P-GP  [AFTE14P-75]  133.13 96.77 0 top
AFTP6238  AFTE14P-GP  [AFTE14P-75]  132.27 80.98 0 top
AFTP6239  AFTE14P-GP  [AFTE14P-75]  136.45 81.7 0 top
AFTP6240  AFTE14P-GP  [AFTE14P-75]  135.05 96.77 0 top
AFTP6241  AFTE14P-GP  [AFTE14P-75]  131.16 96.82 0 top
AFTP6242  AFTE14P-GP  [AFTE14P-75]  129.25 97.07 0 top
AFTP6245  AFTE14P-GP  [AFTE14P-75]  195.67 83.78 0 top
AFTP6246  AFTE14P-GP  [AFTE14P-75]  129.13 103.64 0 top
AFTP6247  AFTE14P-GP  [AFTE14P-75]  129.13 105.55 0 top
AFTP6248  AFTE14P-GP  [AFTE14P-75]  129.13 101.74 0 top
AFTP6801  AFTE14P-GP  [AFTE14P-75]  98.85 132.02 0 top
AFTP6802  AFTE14P-GP  [AFTE14P-75]  99.39 140.43 0 top
BAT1  ALP-CON9-6-GP-U  [C144LC-109A7-L-U]  133.2 155.4 0 bottom
C1  HOLE197R166-1-GP  [HOLE197R166]  97.48 104.66 0 top
C2  HOLE197R166-1-GP  [HOLE197R166]  124.67 72.67 0 top
C3  HOLE197R166-1-GP  [HOLE197R166]  70.29 72.67 0 top
C701  SC22U6D3V5MX-2GP  [C805H58]  107.18 83.29 180 top
C702  SCD1U16V2KX-3GP  [C402H22]  76.1 95.74 0 top
C703  SC1U10V2KX-1GP  [C402H22]  105.87 82.77 180 top
C1001  SC10U10V5KX-2GP  [C805H54]  104.09 65.22 90 top
C1002  SC10U10V5KX-2GP  [C805H54]  76.48 63.36 270 top
C1003  SC10U10V5KX-2GP  [C805H54]  76.48 65.18 270 top
C1004  SC10U10V5KX-2GP  [C805H54]  76.49 61.54 270 top
C1005  SC10U10V5KX-2GP  [C805H54]  104.06 61.51 90 top
C1006  SC10U10V5KX-2GP  [C805H54]  104.06 63.35 90 top
C1017  SC2D2U6D3V2MX-GP  [C402H22]  98.65 78.43 270 top
C1018  SC2D2U6D3V2MX-GP  [C402H22]  101.06 78.41 90 top
C1019  SC2D2U6D3V2MX-GP  [C402H22]  103.06 78.43 90 top
C1020  SC2D2U6D3V2MX-GP  [C402H22]  96.07 78.39 270 top
C1101  SC1U10V2KX-1GP  [C402H22]  117.59 93.17 0 top
C1102  SC1U10V2KX-1GP  [C402H22]  120.43 96.45 90 top
C1103  SC1U10V2KX-1GP  [C402H22]  113.13 99.89 270 bottom
C1104  SC10U10V5KX-2GP  [C805H54]  113.61 101.24 270 bottom
C1105  SC1U10V2KX-1GP  [C402H22]  114.45 99.13 0 bottom
C1106  SC10U10V5KX-2GP  [C805H54]  117.36 101.03 270 bottom
C1107  SC10U10V5KX-2GP  [C805H54]  117.36 102.94 270 bottom
C1108  SC10U10V5KX-2GP  [C805H54]  127.14 82.07 270 bottom
C1109  SC1U10V2KX-1GP  [C402H22]  105.59 87.22 0 top
C1110  SC10U10V5KX-2GP  [C805H54]  107.69 104.01 90 top
C1111  SC1U10V2KX-1GP  [C402H22]  106.51 89.91 180 top
C1112  SC10U10V5KX-2GP  [C805H54]  113.64 101.85 90 top
C1113  SC1U10V2KX-1GP  [C402H22]  108.76 101.31 270 top
C1114  SC10U10V5KX-2GP  [C805H54]  110.61 102.91 90 top
C1115  SC10U10V5KX-2GP  [C805H54]  102.54 81.35 270 top
C1116  SC1U10V2KX-1GP  [C402H22]  109.1 81.1 180 top
C1117  SC1U10V2KX-1GP  [C402H22]  112.35 97.11 180 top
C1118  SC1U10V2KX-1GP  [C402H22]  113.18 97.11 180 top
C1119  SC10U10V5KX-2GP  [C805H54]  114.51 97.3 180 top
C1120  SCD1U16V2KX-3GP  [C402H22]  122.3 55.39 90 top
C1121  SCD1U16V2KX-3GP  [C402H22]  114.75 64.97 270 top
C1122  SC1U10V2KX-1GP  [C402H22]  114.64 65.79 270 top
C1123  SC10U10V5KX-2GP  [C805H54]  113.61 103.14 270 bottom
C1124  SC10U10V5KX-2GP  [C805H54]  107.69 105.86 90 top
C1125  SC10U10V5KX-2GP  [C805H54]  113.64 103.65 90 top
C1201  SCD1U16V2KX-3GP  [C402H22]  90.88 23.56 90 top
C1202  SCD1U16V2KX-3GP  [C402H22]  90.88 21.79 90 top
C1203  SCD1U16V2KX-3GP  [C402H22]  111.61 33.1 270 top
C1204  SCD1U16V2KX-3GP  [C402H22]  49.19 30.51 270 top
C1205  SC2D2U10V3KX-1GP  [C603H36]  49.22 33.09 270 top
C1206  SCD1U16V2KX-3GP  [C402H22]  49.2 31.36 270 top
C1207  SC10U10V5KX-2GP  [C805H54]  67.13 30.91 270 top
C1208  SC10U10V5KX-2GP  [C805H54]  90.62 30.93 90 top
C1209  SC10U10V5KX-2GP  [C805H54]  90.65 33.49 90 top
C1210  SCD1U16V2KX-3GP  [C402H22]  82.12 30.68 0 top
C1211  SCD1U16V2KX-3GP  [C402H22]  80.59 22.93 180 top
C1212  SC1U10V2KX-1GP  [C402H22]  90.5 26.19 90 top
C1213  SC1U10V2KX-1GP  [C402H22]  81.26 32.22 180 top
C1214  SC1U10V2KX-1GP  [C402H22]  111.64 23.38 270 top
C1215  SC1U10V2KX-1GP  [C402H22]  111.56 29.24 270 top
C1216  SC1U10V2KX-1GP  [C402H22]  111.56 28.35 270 top
C1217  SCD1U16V2KX-3GP  [C402H22]  58.87 26.23 180 top
C1218  SCD1U16V2KX-3GP  [C402H22]  90.88 22.67 90 top
C1220  SCD1U16V2KX-3GP  [C402H22]  83.51 26.61 0 top
C1221  SCD1U16V2KX-3GP  [C402H22]  76.15 30.68 0 top
C1222  SCD1U16V2KX-3GP  [C402H22]  75.13 23.06 180 top
C1601  SCD1U16V2KX-3GP  [C402H22]  100.07 99.79 180 bottom
C1602  SCD1U16V2KX-3GP  [C402H22]  99.18 99.79 180 bottom
C1603  SCD1U16V2KX-3GP  [C402H22]  101.22 97.24 180 bottom
C1604  SCD1U16V2KX-3GP  [C402H22]  100.33 97.25 180 bottom
C1605  SCD1U16V2KX-3GP  [C402H22]  108.12 100.81 180 bottom
C1606  SCD1U16V2KX-3GP  [C402H22]  107.23 100.81 180 bottom
C1607  SCD1U16V2KX-3GP  [C402H22]  106.34 100.81 180 bottom
C1608  SCD1U16V2KX-3GP  [C402H22]  105.45 100.81 180 bottom
C1609  SCD1U16V2KX-3GP  [C402H22]  111.19 105.08 180 bottom
C1610  SCD1U16V2KX-3GP  [C402H22]  110.3 105.08 180 bottom
C1611  SCD1U16V2KX-3GP  [C402H22]  109.96 103.08 180 bottom
C1612  SCD1U16V2KX-3GP  [C402H22]  109.09 103.09 180 bottom
C1701  SC220P50V2KX-3GP  [C402H22]  129.98 85.36 90 bottom
C1801  SC15P50V2JN-2-GP  [C402H22]  101.93 101.58 270 bottom
C1802  SC15P50V2JN-2-GP  [C402H22]  103.8 101.57 90 bottom
C1901  SC1U10V2KX-1GP  [C402H22]  119.43 65.27 180 top
C1902  SC1U10V2KX-1GP  [C402H22]  118.56 65.28 180 top
C1903  SC15P50V2JN-2-GP  [C402H22]  122.03 66.6 180 bottom
C1904  SC15P50V2JN-2-GP  [C402H22]  122.03 64.9 0 bottom
C2101  SCD47U6D3V2KX-GP  [C402H22]  108.16 75.48 180 top
C2104  SC1U10V2KX-1GP  [C402H22]  119.35 89.61 0 top
C2105  SC1U10V2KX-1GP  [C402H22]  122.25 98.75 90 top
C2109  SC1U10V2KX-1GP  [C402H22]  115.39 59.5 0 top
C2110  SCD1U16V2KX-3GP  [C402H22]  125.02 78.53 0 bottom
C2114  SC1U10V2KX-1GP  [C402H22]  106.27 75.49 180 top
C2116  SC1U10V2KX-1GP  [C402H22]  108.95 76.88 270 top
C2123  SC10U6D3V3MX-GP  [C603H38]  127.2 87.21 90 bottom
C2128  SC1U10V2KX-1GP  [C402H22]  109.88 82.95 0 top
C2135  SC1U10V2KX-1GP  [C402H22]  121.75 103.21 180 bottom
C2136  SCD1U16V2KX-3GP  [C402H22]  121.05 65.41 90 top
C2137  SC1U10V2KX-1GP  [C402H22]  115.92 101.29 270 top
C2138  SC1U10V2KX-1GP  [C402H22]  105.21 105.9 0 top
C2141  SC4D7U6D3V3KX-GP  [C603H36]  128.09 100.65 270 bottom
C2142  SC10U10V5KX-2GP  [C805H54]  122.5 107.64 0 bottom
C2147  SCD1U16V2KX-3GP  [C402H22]  132.33 89.73 90 bottom
C2401  SCD1U16V2KX-3GP  [C402H22]  181.69 29.03 90 top
C2402  SCD1U16V2KX-3GP  [C402H22]  165.31 18.83 270 top
C2403  SCD1U16V2KX-3GP  [C402H22]  160.3 22.61 180 top
C2404  SCD1U16V2KX-3GP  [C402H22]  165.95 17.57 180 top
C2405  SC2D2U10V3KX-1GP  [C603H36]  164.91 17.22 180 top
C2406  SCD1U16V2KX-3GP  [C402H22]  160.76 32.04 270 bottom
C2407  SCD1U16V2KX-3GP  [C402H22]  160.76 32.93 270 bottom
C2408  SCD1U16V2KX-3GP  [C402H22]  170.56 37.63 0 bottom
C2409  SCD1U16V2KX-3GP  [C402H22]  171.39 37.63 0 bottom
C2410  SCD1U16V2KX-3GP  [C402H22]  177.65 32.87 180 bottom
C2411  SC2D2U10V3KX-1GP  [C603H36]  158.48 31.87 270 top
C2412  SCD1U16V2KX-3GP  [C402H22]  180.79 24.94 180 top
C2413  SC2D2U10V3KX-1GP  [C603H36]  181.87 24.91 180 top
C2414  SCD1U16V2KX-3GP  [C402H22]  163.53 20.13 90 top
C2415  SC220P50V2KX-3GP  [C402H22]  178.14 27.02 180 bottom
C2416  SC1U10V2KX-1GP  [C402H22]  171.08 39.9 0 top
C2417  SCD1U16V2KX-3GP  [C402H22]  154.47 29.71 90 top
C2418  SC1U10V2KX-1GP  [C402H22]  158.65 27.25 180 top
C2421  SC47P50V2JN-3GP  [C402H22]  188.05 35.69 0 top
C2422  SC100P50V2JN-3GP  [C402H22]  184.11 31.55 180 top
C2501  SC10U10V5KX-2GP  [C805H54]  154 36.52 180 bottom
C2502  SCD1U16V2KX-3GP  [C402H22]  154 38.42 270 bottom
C2503  SCD47U6D3V2KX-GP  [C402H22]  54.26 5.25 90 bottom
C2601  SC10U6D3V3MX-GP  [C603H38]  113.38 112.62 270 top
C2602  SCD1U16V2KX-3GP  [C402H22]  117.6 112.21 180 bottom
C2603  SC2200P50V2KX-2GP  [C402H22]  40.33 91.76 180 bottom
C2604  SC4D7U6D3V3KX-GP  [C603H36]  39.19 91.51 180 bottom
C2605  SCD1U16V2KX-3GP  [C402H22]  37.41 94.94 270 bottom
C2606  SC470P50V3JN-2GP  [C603H36]  46.28 36.91 90 top
C2607  SC2200P50V2KX-2GP  [C402H22]  114.45 110.33 0 top
C2608  SCD1U16V2KX-3GP  [C402H22]  125.09 62.38 270 top
C2609  SCD1U16V2KX-3GP  [C402H22]  126.99 62.38 90 top
C2610  SCD1U16V2KX-3GP  [C402H22]  155.8 23.52 90 top
C2611  SC4D7U6D3V3KX-GP  [C603H36]  37.79 93.79 270 bottom
C2612  SCD1U16V2KX-3GP  [C402H22]  109.67 61.36 270 bottom
C2613  SC100P50V2JN-3GP  [C402H22]  165.94 22.22 180 bottom
C2701  SC4D7U6D3V3KX-GP  [C603H36]  30.8 5.61 180 bottom
C2702  SC4D7U6D3V3KX-GP  [C603H36]  29.33 13.31 90 top
C2703  SC1U10V2KX-1GP  [C402H22]  30.93 6.55 0 top
C2704  SC1U10V2KX-1GP  [C402H22]  29.41 8.32 90 top
C2705  SC2D2U6D3V2MX-GP  [C402H22]  29.67 12.25 90 top
C2706  SC4D7U6D3V3KX-GP  [C603H36]  34.96 3.26 0 top
C2707  SCD1U16V2KX-3GP  [C402H22]  36.05 2.93 0 top
C2708  SC4D7U6D3V3KX-GP  [C603H36]  39.45 2.68 270 top
C2709  SCD1U16V2KX-3GP  [C402H22]  36.9 2.93 0 top
C2710  SCD1U16V2KX-3GP  [C402H22]  29.03 15.18 180 top
C2711  SC4D7U6D3V3KX-GP  [C603H36]  30.14 15.14 180 top
C2712  SC10U6D3V3MX-GP  [C603H38]  30.21 4.01 180 top
C2713  SC10U6D3V3MX-GP  [C603H38]  33.53 18.05 180 top
C2715  SC4D7U6D3V3KX-GP  [C603H36]  33.28 4.19 0 top
C2716  SC4D7U6D3V3KX-GP  [C603H36]  41.74 5.77 90 top
C2717  SCD1U16V2KX-3GP  [C402H22]  40.08 6.93 180 top
C2718  SC4D7U6D3V3KX-GP  [C603H36]  42.12 11.52 90 top
C2719  SCD1U16V2KX-3GP  [C402H22]  41.22 13.39 90 top
C2720  SCD1U16V2KX-3GP  [C402H22]  39.49 16.55 270 top
C2723  SC22P50V2JN-4GP  [C402H22]  43.29 8.43 270 top
C2901  SC1U10V2KX-1GP  [C402H22]  42.04 17.26 180 top
C2902  SC10U6D3V3MX-GP  [C603H38]  17.98 7.94 180 bottom
C2907  SC4D7U6D3V3KX-GP  [C603H36]  29.67 17 270 top
C2908  SC4D7U6D3V3KX-GP  [C603H36]  29.66 18.31 270 top
C3001  SC15P50V2JN-2-GP  [C402H22]  45.24 60.74 0 bottom
C3002  SCD1U16V2KX-3GP  [C402H22]  43.87 64.09 0 bottom
C3003  SCD1U16V2KX-3GP  [C402H22]  44.85 68.01 0 bottom
C3004  SC4D7U6D3V3KX-GP  [C603H36]  41.74 53.64 0 top
C3005  SC4D7U6D3V3KX-GP  [C603H36]  35.49 59.08 90 bottom
C3007  SCD1U16V2KX-3GP  [C402H22]  39.25 59.93 90 top
C3008  SCD1U16V2KX-3GP  [C402H22]  42.64 56.92 180 bottom
C3009  SCD1U16V2KX-3GP  [C402H22]  41.37 66.75 0 bottom
C3010  SC4D7U6D3V3KX-GP  [C603H36]  42.43 66.86 0 bottom
C3011  SC15P50V2JN-2-GP  [C402H22]  45.24 58.96 180 bottom
C3012  SC4D7U6D3V3KX-GP  [C603H36]  41.35 66.49 180 top
C3013  SCD1U16V2KX-3GP  [C402H22]  38.35 49.32 0 top
C3014  SCD1U16V2KX-3GP  [C402H22]  38.61 66.51 0 bottom
C3015  SC1U10V2KX-1GP  [C402H22]  37.23 50.57 270 top
C3016  SCD1U16V2KX-3GP  [C402H22]  39.5 66.51 0 bottom
C3017  SCD1U16V2KX-3GP  [C402H22]  40.59 53.53 0 top
C3018  SC1U10V2KX-1GP  [C402H22]  40.9 62.98 0 top
C3019  SCD1U16V2KX-3GP  [C402H22]  40.14 58.53 180 top
C3021  SCD1U16V2KX-3GP  [C402H22]  41.66 58.47 180 top
C3022  SCD1U16V2KX-3GP  [C402H22]  41.79 62.98 0 top
C3023  SCD1U16V2KX-3GP  [C402H22]  42.42 61.71 270 top
C3024  SCD1U16V2KX-3GP  [C402H22]  42.42 60.69 270 top
C3025  SCD1U16V2KX-3GP  [C402H22]  42.42 59.8 270 top
C3101  SC100P3KV8JN-2-GP  [C1808H56]  26.93 46.74 90 top
C3106  SCD01U50V2KX-1GP  [C402H22]  32.54 48.48 270 bottom
C3401  SC4D7P50V2CN-1GP  [C402H22]  22.58 28.95 0 bottom
C3402  SC4D7P50V2CN-1GP  [C402H22]  22.58 27.17 180 bottom
C3403  SCD1U16V2KX-3GP  [C402H22]  28.78 27.47 90 bottom
C3404  SCD1U16V2KX-3GP  [C402H22]  28.78 28.36 90 bottom
C3405  SCD1U16V2KX-3GP  [C402H22]  18.06 27.14 0 top
C3406  SCD1U16V2KX-3GP  [C402H22]  25.55 34.76 90 top
C3501  SCD1U16V2KX-3GP  [C402H22]  33.26 28.54 0 top
C3502  SC1U10V2KX-1GP  [C402H22]  34.41 28.41 0 top
C3503  SCD1U16V2KX-3GP  [C402H22]  25.54 33.9 90 top
C3504  SCD1U16V2KX-3GP  [C402H22]  145.23 5.7 180 bottom
C3505  SC1U10V2KX-1GP  [C402H22]  41.61 31.53 90 top
C3506  SC1U10V2KX-1GP  [C402H22]  25.55 35.88 90 top
C3507  SCD1U16V2KX-3GP  [C402H22]  18.95 27.12 0 top
C3508  SC1U10V2KX-1GP  [C402H22]  22.76 30.95 180 top
C3509  SC22U6D3V5MX-2GP  [C805H58]  17.26 38.73 0 top
C3510  SC1U10V2KX-1GP  [C402H22]  146.3 5.66 180 bottom
C3512  SC22U6D3V5MX-2GP  [C805H58]  21.18 27.53 0 top
C3513  SC22U6D3V5MX-2GP  [C805H58]  21.18 30.88 180 top
C3514  SC22U6D3V5MX-2GP  [C805H58]  19.19 38.73 0 top
C3515  SC22U6D3V5MX-2GP  [C805H58]  186.13 5.15 180 bottom
C3516  SC22U6D3V5MX-2GP  [C805H58]  184.22 5.15 180 bottom
C3517  SCD1U16V2KX-3GP  [C402H22]  159.33 4.99 180 bottom
C3518  SC1U10V2KX-1GP  [C402H22]  161.36 5.12 180 bottom
C3601  SC470P50V2KX-3GP  [C402H22]  129.84 3.27 270 top
C3602  SC470P50V2KX-3GP  [C402H22]  131.54 3.29 90 top
C3603  SC10U10V5KX-2GP  [C805H54]  136.03 5.97 180 top
C3604  SCD1U16V2KX-3GP  [C402H22]  154.56 18.45 180 top
C3605  SC10U10V5KX-2GP  [C805H54]  127.01 3.48 0 top
C3701  SCD022U16V2KX-3GP  [C402H22]  67.64 53.28 270 top
C3702  SCD022U16V2KX-3GP  [C402H22]  56.79 39.13 270 top
C3801  SC1U10V2KX-1GP  [C402H22]  135.2 57.73 90 bottom
C3802  SC1U10V2KX-1GP  [C402H22]  134.69 65.35 90 bottom
C5201  SCD1U16V2KX-3GP  [C402H22]  49.58 79.67 90 top
C5202  SC1KP50V2KX-1GP  [C402H22]  51.96 84.97 180 top
C5203  SCD1U16V2KX-3GP  [C402H22]  40.82 77.85 180 top
C5204  SC4D7U6D3V3KX-GP  [C603H36]  51.06 70.98 90 top
C5205  SCD1U50V3KX-GP  [C603H36]  53.1 84.97 0 top
C5206  SC1U10V2KX-1GP  [C402H22]  49.58 80.56 270 top
C5207  SC4D7U6D3V3KX-GP  [C603H36]  17.98 90.87 270 bottom
C5208  SC10P50V2JN-4GP  [C402H22]  38.12 81.39 0 bottom
C5209  SCD1U16V2KX-3GP  [C402H22]  41.84 77.9 180 top
C5210  SCD1U16V2KX-3GP  [C402H22]  39.93 77.85 180 top
C5211  SCD1U16V2KX-3GP  [C402H22]  38.71 77.79 180 top
C5212  SCD1U16V2KX-3GP  [C402H22]  42.73 77.9 180 top
C5213  SCD1U16V2KX-3GP  [C402H22]  37.82 77.79 180 top
C5214  SC10P50V2JN-4GP  [C402H22]  36.51 81.38 0 bottom
C5401  SCD1U16V2KX-3GP  [C402H22]  16.76 82.54 90 bottom
C5402  SCD1U16V2KX-3GP  [C402H22]  22.04 79.44 90 bottom
C5403  SCD1U16V2KX-3GP  [C402H22]  22.04 78.55 90 bottom
C5404  SCD1U16V2KX-3GP  [C402H22]  21.96 77.67 90 bottom
C5405  SCD1U16V2KX-3GP  [C402H22]  21.96 76.78 90 bottom
C5406  SCD1U16V2KX-3GP  [C402H22]  21.61 74.9 90 bottom
C5407  SCD1U16V2KX-3GP  [C402H22]  21.08 73.81 90 bottom
C5408  SCD1U16V2KX-3GP  [C402H22]  21.08 72.98 90 bottom
C5409  SCD1U16V2KX-3GP  [C402H22]  21.61 75.79 90 bottom
C5602  SCD01U50V2KX-1GP  [C402H22]  188.03 8.96 90 bottom
C5603  SCD01U50V2KX-1GP  [C402H22]  188.03 9.85 90 bottom
C5605  SC10U10V5KX-2GP  [C805H54]  189.99 29.84 270 top
C5606  SCD1U16V2KX-3GP  [C402H22]  190.18 31.16 270 top
C5607  SCD01U50V2KX-1GP  [C402H22]  195.91 71.7 90 bottom
C5608  SCD01U50V2KX-1GP  [C402H22]  195.91 72.59 90 bottom
C5609  SC10U10V5KX-2GP  [C805H54]  191.59 73.96 90 bottom
C5610  SC10U10V5KX-2GP  [C805H54]  193.49 84.02 90 bottom
C5611  SCD01U50V2KX-1GP  [C402H22]  195.91 70.55 90 bottom
C5612  SCD01U50V2KX-1GP  [C402H22]  195.91 69.66 90 bottom
C5615  SCD01U50V2KX-1GP  [C402H22]  188.02 11.6 270 bottom
C5616  SCD01U50V2KX-1GP  [C402H22]  188.02 10.71 270 bottom
C5802  SCD1U16V2KX-3GP  [C402H22]  181.89 14.8 270 bottom
C5803  SC10U10V5KX-2GP  [C805H54]  181.9 13.47 270 bottom
C5804  SCD1U16V2KX-3GP  [C402H22]  177.81 39.58 180 bottom
C5807  SCD1U16V2KX-3GP  [C402H22]  185.69 41.08 270 top
C6201  SCD1U16V2KX-3GP  [C402H22]  132.87 74.74 180 top
C6202  SCD1U16V2KX-3GP  [C402H22]  137.77 79.21 90 bottom
C6203  SCD1U16V2KX-3GP  [C402H22]  139.8 79.72 270 bottom
C6204  SCD1U16V2KX-3GP  [C402H22]  140.28 87.7 270 bottom
C6401  SCD047U25V2KX-GP  [C402H22]  12.03 74.63 90 top
C6402  SCD1U16V2KX-3GP  [C402H22]  12.08 75.08 180 bottom
C7301  SCD22U10V2KX-1GP  [C402H22]  155.65 107.64 90 top
C7302  SCD22U10V2KX-1GP  [C402H22]  155.65 108.53 90 top
C7303  SCD22U10V2KX-1GP  [C402H22]  154.98 109.39 90 top
C7304  SCD22U10V2KX-1GP  [C402H22]  154.98 110.28 90 top
C7305  SCD22U10V2KX-1GP  [C402H22]  155.9 112.39 90 top
C7306  SCD22U10V2KX-1GP  [C402H22]  155.9 113.28 90 top
C7307  SCD22U10V2KX-1GP  [C402H22]  156.46 114.42 90 top
C7308  SCD22U10V2KX-1GP  [C402H22]  156.46 115.31 90 top
C7309  SC4D7U6D3V3KX-GP  [C603H36]  159.97 120.26 270 top
C7310  SC4D7U6D3V3KX-GP  [C603H36]  156.85 120.19 90 top
C7311  SC1U10V2KX-1GP  [C402H22]  163.17 118.74 90 top
C7312  SC1U10V2KX-1GP  [C402H22]  160.35 118.23 270 top
C7313  SC1U10V2KX-1GP  [C402H22]  160.35 119.12 270 top
C7314  SC1U10V2KX-1GP  [C402H22]  163.17 117.87 90 top
C7315  SC4D7U6D3V3KX-GP  [C603H36]  162.98 111.3 90 top
C7316  SCD1U16V2KX-3GP  [C402H22]  163.04 110.14 90 top
C7317  SC4D7U6D3V3KX-GP  [C603H36]  163.01 116.83 90 top
C7318  SCD1U16V2KX-3GP  [C402H22]  163.19 115.69 90 top
C7319  SC1U10V2KX-1GP  [C402H22]  163.19 114.8 90 top
C7320  SC10U6D3V3MX-GP  [C603H38]  157.41 118.54 90 top
C7321  SC10U6D3V3MX-GP  [C603H38]  160 129.82 180 top
C7322  SC10U6D3V3MX-GP  [C603H38]  154.61 125.85 270 top
C7323  SC10U6D3V3MX-GP  [C603H38]  162.87 127.03 90 top
C7324  SC4D7U6D3V3KX-GP  [C603H36]  172.63 113.37 270 top
C7325  SC10U6D3V3MX-GP  [C603H38]  152.85 124.56 90 bottom
C7326  SC10U6D3V3MX-GP  [C603H38]  158.1 129.82 180 top
C7327  SC10U6D3V3MX-GP  [C603H38]  154.58 127.69 270 top
C7328  SC10U6D3V3MX-GP  [C603H38]  162.87 128.86 90 top
C7501  SCD1U16V2KX-3GP  [C402H22]  173.19 123.84 180 top
C7502  SCD1U16V2KX-3GP  [C402H22]  172.41 115.69 0 top
C7503  SCD1U16V2KX-3GP  [C402H22]  170.26 124.09 90 top
C7504  SCD1U16V2KX-3GP  [C402H22]  163 120.94 270 top
C7505  SCD1U16V2KX-3GP  [C402H22]  174.19 115.44 0 top
C7506  SCD1U16V2KX-3GP  [C402H22]  169.26 121.48 90 top
C7507  SC1U10V2KX-1GP  [C402H22]  170.04 125.36 0 top
C7511  SCD1U16V2KX-3GP  [C402H22]  189.25 151.83 270 bottom
C7513  SC4D7U6D3V3KX-GP  [C603H36]  144.83 142.92 270 top
C7514  SC4D7U6D3V3KX-GP  [C603H36]  172.79 117.6 270 top
C7515  SC1U10V2KX-1GP  [C402H22]  155.81 135.72 270 top
C7516  SC1U10V2KX-1GP  [C402H22]  189.24 151.01 270 bottom
C7517  SC10U10V5KX-2GP  [C805H54]  180.64 125.94 0 top
C7518  SC22U6D3V5MX-2GP  [C805H58]  167.34 120.13 90 top
C7519  SC1U10V2KX-1GP  [C402H22]  179.29 126.18 180 top
C7520  SC22U6D3V5MX-2GP  [C805H58]  170.25 120.13 270 top
C7521  SC1U10V2KX-1GP  [C402H22]  144.66 144.87 270 top
C7525  SC1U10V2KX-1GP  [C402H22]  172.79 114.42 270 top
C7526  SCD1U16V2KX-3GP  [C402H22]  182.33 151.43 180 top
C7527  SC1U10V2KX-1GP  [C402H22]  183.49 151.43 180 top
C7528  SC1U10V2KX-1GP  [C402H22]  149.2 151.02 0 bottom
C7530  SC1U10V2KX-1GP  [C402H22]  163.89 151.25 0 bottom
C7531  SC1U10V2KX-1GP  [C402H22]  184.44 151.41 180 top
C7601  SCD1U16V2KX-3GP  [C402H22]  167.97 110.1 270 top
C7602  SCD1U16V2KX-3GP  [C402H22]  169.36 110.48 180 top
C7603  SC4D7U6D3V3KX-GP  [C603H36]  168.23 102.61 270 top
C7604  SC10U6D3V3MX-GP  [C603H38]  168.23 103.88 270 top
C7605  SCD1U16V2KX-3GP  [C402H22]  172.16 108.49 90 top
C7606  SC2D2U6D3V2MX-GP  [C402H22]  172.16 107.61 90 top
C7607  SC15P50V2JN-2-GP  [C402H22]  183.13 112.77 180 bottom
C7608  SC15P50V2JN-2-GP  [C402H22]  183.13 109.33 0 bottom
C7609  SC2700P50V2KX-1-GP  [C402H22]  188.9 101.69 180 bottom
C7610  SC2700P50V2KX-1-GP  [C402H22]  189.38 105.07 90 bottom
C7701  SC4D7U6D3V3KX-GP  [C603H36]  167.33 112.77 0 top
C7702  SC4D7U6D3V3KX-GP  [C603H36]  167.33 115.18 0 top
C7703  SC4D7U6D3V3KX-GP  [C603H36]  192.63 104.35 270 bottom
C7708  SC4D7U6D3V3KX-GP  [C603H36]  169.36 112.64 0 top
C7709  SC4D7U6D3V3KX-GP  [C603H36]  169.36 117.47 0 top
C7710  SC47U6D3V5MX-1-GP  [C805H54]  160.61 102.19 270 top
C7711  SCD1U16V2KX-3GP  [C402H22]  171.14 117.34 0 top
C7712  SCD1U16V2KX-3GP  [C402H22]  165.43 111.25 0 top
C7713  SCD1U16V2KX-3GP  [C402H22]  171.14 115.18 0 top
C7714  SCD1U16V2KX-3GP  [C402H22]  165.43 113.02 0 top
C7717  SC22U6D3V5MX-2GP  [C805H58]  160.61 104.01 270 top
C7719  SC4D7U6D3V3KX-GP  [C603H36]  172.95 103.54 180 top
C7720  SC4D7U6D3V3KX-GP  [C603H36]  160.51 97.93 270 top
C7721  SC4D7U6D3V3KX-GP  [C603H36]  176.08 98.56 180 top
C7722  SC4D7U6D3V3KX-GP  [C603H36]  160.52 99.25 270 top
C7723  SC4D7U6D3V3KX-GP  [C603H36]  165.43 117.6 0 top
C7724  SC4D7U6D3V3KX-GP  [C603H36]  169.36 115.06 0 top
C7725  SC4D7U6D3V3KX-GP  [C603H36]  165.43 115.18 0 top
C7726  SC4D7U6D3V3KX-GP  [C603H36]  167.33 117.6 0 top
C7727  SCD1U16V2KX-3GP  [C402H22]  172.75 112.32 270 top
C7728  SC1U10V2KX-1GP  [C402H22]  174.03 110.32 0 top
C7729  SCD1U16V2KX-3GP  [C402H22]  172.75 111.51 270 top
C7730  SC4D7U6D3V3KX-GP  [C603H36]  160.51 96.62 270 top
C7731  SC4D7U6D3V3KX-GP  [C603H36]  173.17 99.66 90 top
C7732  SC10U6D3V3MX-GP  [C603H38]  160.52 100.53 270 top
C7733  ST330U2VDM-4-GP  [CT7343H79]  184.1 91.89 270 bottom
C7734  SCD1U16V2KX-3GP  [C402H22]  172.76 110.21 270 top
C7803  SC820P50V2KX-1GP  [C402H22]  174.94 151.61 270 bottom
C7804  SCD1U16V2KX-3GP  [C402H22]  180.98 151.18 0 bottom
C7805  SC1U6D3V3KX-2GP  [C603H36]  184.69 151.44 0 bottom
C7810  SC1U6D3V3KX-2GP  [C603H36]  154.37 152.62 180 top
C7811  SC1U6D3V3KX-2GP  [C603H36]  191.34 141.04 90 top
C7812  SC1U6D3V3KX-2GP  [C603H36]  150.46 152.58 180 top
C7813  SC10U6D3V3MX-GP  [C603H38]  172.81 134.52 180 bottom
C7814  SC1U6D3V3KX-2GP  [C603H36]  171.49 152.61 180 top
C7815  SC10U6D3V3MX-GP  [C603H38]  170.94 134.51 180 bottom
C7816  SC1U6D3V3KX-2GP  [C603H36]  153.02 152.63 180 top
C7817  SC1U6D3V3KX-2GP  [C603H36]  196.8 132.66 270 bottom
C7820  SCD1U16V2KX-3GP  [C402H22]  160.59 135.75 270 top
C7821  SCD1U16V2KX-3GP  [C402H22]  173.55 152.54 180 top
C7822  SC1U6D3V3KX-2GP  [C603H36]  181.07 151.76 180 top
C7827  SCD1U16V2KX-3GP  [C402H22]  183.21 120.9 0 top
C7829  SCD1U16V2KX-3GP  [C402H22]  162.38 135.74 90 top
C7830  SCD1U16V2KX-3GP  [C402H22]  196.8 133.83 270 bottom
C7831  SCD1U16V2KX-3GP  [C402H22]  173.38 134.24 0 top
C7832  SCD1U16V2KX-3GP  [C402H22]  150.26 151.02 0 bottom
C7833  SCD1U16V2KX-3GP  [C402H22]  172.68 152.52 180 top
C7834  SCD1U16V2KX-3GP  [C402H22]  145.94 148.43 90 bottom
C7835  SCD1U16V2KX-3GP  [C402H22]  183.64 151.17 0 bottom
C7836  SCD1U16V2KX-3GP  [C402H22]  174.39 152.54 180 top
C7902  SC820P50V2KX-1GP  [C402H22]  154.43 151.11 0 bottom
C7906  SC1U6D3V3KX-2GP  [C603H36]  185.99 151.44 0 bottom
C7909  SCD1U16V2KX-3GP  [C402H22]  175.4 134.46 180 bottom
C7910  SCD1U16V2KX-3GP  [C402H22]  150.51 135.69 270 top
C7911  SC1U6D3V3KX-2GP  [C603H36]  148.92 152.56 180 top
C7912  SCD1U16V2KX-3GP  [C402H22]  144.65 144.02 270 top
C7913  SCD1U16V2KX-3GP  [C402H22]  179.45 134.58 0 top
C7915  SC1U6D3V3KX-2GP  [C603H36]  179.84 151.46 0 bottom
C7916  SC1U6D3V3KX-2GP  [C603H36]  180.85 134.71 0 top
C7917  SC1U6D3V3KX-2GP  [C603H36]  164.41 152.43 180 top
C7918  SC10U10V5KX-2GP  [C805H54]  172.06 134.47 0 top
C7919  SC1U6D3V3KX-2GP  [C603H36]  145.81 149.53 90 bottom
C7920  SC10U10V5KX-2GP  [C805H54]  144.91 141.35 270 top
C7921  SCD1U16V2KX-3GP  [C402H22]  152.36 135.75 270 top
C7922  SCD1U16V2KX-3GP  [C402H22]  178.61 134.58 0 top
C7923  SCD1U16V2KX-3GP  [C402H22]  151.58 151.02 0 bottom
C7924  SC1U6D3V3KX-2GP  [C603H36]  162.77 151.6 0 bottom
C7925  SCD1U16V2KX-3GP  [C402H22]  196.88 129.45 270 bottom
C7926  SC1U6D3V3KX-2GP  [C603H36]  176.52 134.44 180 bottom
C7927  SCD1U16V2KX-3GP  [C402H22]  189.24 150.2 270 bottom
C7928  SCD1U16V2KX-3GP  [C402H22]  191.34 142.18 90 top
C7929  SCD1U16V2KX-3GP  [C402H22]  151.6 152.54 180 top
C7930  SCD1U16V2KX-3GP  [C402H22]  174.51 134.48 180 bottom
C8301  SCD01U50V2KX-1GP  [C402H22]  194.26 100.82 180 bottom
C8302  SC1U10V2KX-1GP  [C402H22]  147.79 122.2 270 top
C8303  SCD1U16V2KX-3GP  [C402H22]  192.54 105.42 270 bottom
C8304  SC1U10V2KX-1GP  [C402H22]  148.33 118.79 0 top
C8305  SC470P50V2KX-3GP  [C402H22]  153.94 119.58 0 top
C8306  SCD1U16V2KX-3GP  [C402H22]  162.93 125.65 270 top
C8307  SC10U10V5KX-2GP  [C805H54]  150.19 117.85 270 top
C8308  SCD1U16V2KX-3GP  [C402H22]  150.19 116.5 270 top
C8309  SCD1U16V2KX-3GP  [C402H22]  147.79 121.36 90 top
C8310  SC10U10V5KX-2GP  [C805H54]  150.97 124.21 270 top
C8311  SCD1U16V2KX-3GP  [C402H22]  189.78 100.8 0 bottom
C8316  SC2200P50V2KX-2GP  [C402H22]  153.94 121.32 0 top
C9602  SCD1U16V2KX-3GP  [C402H22]  124.12 81.55 270 bottom
CCD1  DM-ACES-CON8-44-GP-01  [DM-4260-F08N-00R-01]  18.5 90.2 180 top
CON1  PTWO-CON16-2-GP  [196353-16021-3]  184.9 12.65 90 top
CPU1  HASWELL-6-GP-U  [BGA1168M4024H64]  99.58 82.4 0 bottom
D2401  RB751V-40-H-GP  [SOD323AKH40]  186.64 24.94 90 top
D2402  RB751V-40-H-GP  [SOD323AKH40]  186.64 26.99 90 top
D2501  BAS40C-2-GP  [SOT-23-9H44]  54.36 7.74 180 bottom
D2601  RB551V30-GP  [SOD323AKH38]  37.54 90.75 0 bottom
D2701  BAT54C-7-F-3-GP  [SOT23-2D4-312H48]  40.46 20.18 180 top
D3602  BAS16-6-GP  [SOT23-2D4-312H44]  152.75 21.97 270 top
D4301  LBAV99LT1G-1-GP  [SOT23-2D4-312H44]  134.78 145.48 90 top
D4302  LBAV99LT1G-1-GP  [SOT23-2D4-312H44]  126.26 148.28 270 top
D4303  LBAV99LT1G-1-GP  [SOT23-2D4-312H44]  130.69 145.48 270 top
D5201  BAT54C-7-F-3-GP  [SOT23-2D4-312H48]  54.2 73.91 0 top
D5202  BAT54C-7-F-3-GP  [SOT23-2D4-312H48]  43.37 79.06 270 bottom
D5401  BAW56-5-GP  [SOT-23-9H44]  26.36 78.71 90 bottom
D7301  BAT54A-1-GP  [SOT23-2D4-312H44]  155.34 104.26 90 top
D7601  1SS400GPT-GP  [SOD723AKH27]  175.1 101.55 0 top
D7602  1SS400GPT-GP  [SOD723AKH27]  176.37 101.55 0 top
D8301  BAT54C-7-F-3-GP  [SOT23-2D4-312H48]  181.81 48.33 90 bottom
DB1  PAD-10P-177042-GP  [PAD-10P-177042]  160.35 11.37 180 bottom
DCIN1  ACES-CON7-6-GP-U  [50299-00701-W01]  97.12 149.7 270 top
DM1  DDR3-204P-48-GP-U  [1932208-1-U]  81.9 26.82 180 bottom
EC701  SCD1U16V2KX-3GP  [C402H22]  81.35 97.99 270 bottom
EC702  SCD1U16V2KX-3GP  [C402H22]  79.58 97.99 90 bottom
EC1501  SC1KP50V2KX-1GP  [C402H22]  125.92 98.34 180 top
EC1502  SC1KP50V2KX-1GP  [C402H22]  129.97 95.45 90 bottom
EC1701  SC4D7P50V2CN-1GP  [C402H22]  130.63 89.73 90 bottom
EC1702  SC1KP50V2KX-1GP  [C402H22]  130.83 90.58 270 bottom
EC1703  SC1KP50V2KX-1GP  [C402H22]  37.7 66.49 180 top
EC1704  SC1KP50V2KX-1GP  [C402H22]  120.42 59.43 180 bottom
EC1705  SC1KP50V2KX-1GP  [C402H22]  125.79 60.74 270 bottom
EC1706  SC1KP50V2KX-1GP  [C402H22]  124.07 80.73 270 bottom
EC1707  SCD1U16V2KX-3GP  [C402H22]  131.79 84.87 180 bottom
EC1801  SC10P50V2JN-4GP  [C402H22]  111.2 59.95 180 top
EC1802  SC10P50V2JN-4GP  [C402H22]  112.21 59.95 180 top
EC1901  SC10P50V2JN-4GP  [C402H22]  118.65 51.9 270 bottom
EC2501  SC4D7P50V2CN-1GP  [C402H22]  157.55 38.42 270 bottom
EC2502  SC4D7P50V2CN-1GP  [C402H22]  148.34 39.04 270 bottom
EC2503  SC10P50V2JN-4GP  [C402H22]  155.78 38.42 90 bottom
EC2601  SCD1U16V2KX-3GP  [C402H22]  41.22 91.76 180 bottom
EC2602  SC10P50V2JN-4GP  [C402H22]  40.21 93.92 180 bottom
EC2701  SC10P50V2JN-4GP  [C402H22]  41.37 6.85 90 top
EC2703  SCD1U25V2KX-GP  [C402H22]  34.1 20.91 180 top
EC2704  SC1KP50V2KX-1GP  [C402H22]  28.29 3.05 0 top
EC2705  SCD1U25V2KX-GP  [C402H22]  34.94 20.9 180 top
EC2706  SC1KP50V2KX-1GP  [C402H22]  29.12 3.05 0 top
EC2707  SC1KP50V2KX-1GP  [C402H22]  37.16 18.48 90 top
EC2708  SCD1U16V2KX-3GP  [C402H22]  41.98 10.61 270 bottom
EC2709  SCD1U16V2KX-3GP  [C402H22]  43.03 10.37 90 top
EC2901  SC2K2P50V3KX-GP  [C603]  74.45 2.76 270 top
EC2902  SC2K2P50V3KX-GP  [C603]  77.43 4.52 180 top
EC2903  SC2K2P50V3KX-GP  [C603]  77.42 7.89 180 top
EC2904  SC2K2P50V3KX-GP  [C603]  76.12 5.86 0 top
EC2905  SC100P50V2JN-3GP  [C402H22]  17.87 5.49 180 top
EC2906  SC100P50V2JN-3GP  [C402H22]  24.28 4.76 180 top
EC2907  SC100P50V2JN-3GP  [C402H22]  27.69 10.72 180 top
EC2908  SC100P50V2JN-3GP  [C402H22]  26.9 13.57 90 top
EC3101  SC10P50V2JN-4GP  [C402H22]  35.43 51.76 0 bottom
EC3102  SC10P50V2JN-4GP  [C402H22]  35.43 53.54 180 bottom
EC3103  SC10P50V2JN-4GP  [C402H22]  35.25 55.82 0 bottom
EC3104  SC10P50V2JN-4GP  [C402H22]  35.25 57.6 180 bottom
EC3105  SC10P50V2JN-4GP  [C402H22]  35.43 51.76 180 top
EC3106  SC10P50V2JN-4GP  [C402H22]  35.43 53.54 0 top
EC3107  SC10P50V2JN-4GP  [C402H22]  35.25 55.82 180 top
EC3108  SC10P50V2JN-4GP  [C402H22]  35.25 57.6 0 top
EC4201  SC10U25V5KX-GP  [C805H56]  104.65 147.95 0 bottom
EC4202  SCD1U25V2KX-GP  [C402H22]  106 148.53 0 bottom
EC4301  SC10P50V2JN-4GP  [C402H22]  133.61 143.07 90 top
EC4302  SC10P50V2JN-4GP  [C402H22]  131.84 143.07 270 top
EC4303  SCD1U25V2KX-GP  [C402H22]  136.11 150.58 90 bottom
EC4304  SCD1U50V3KX-GP  [C603H36]  142.44 150.56 270 bottom
EC4305  SC10P50V2JN-4GP  [C402H22]  123.77 149.29 0 top
EC4401  SC2200P50V2KX-2GP  [C402H22]  115.26 138.37 180 top
EC4402  SCD1U25V2KX-GP  [C402H22]  115.26 138.37 0 bottom
EC4601  SCD1U50V3KX-GP  [C603H36]  82.01 14.5 0 top
EC4701  SCD1U25V2KX-GP  [C402H22]  92.86 102.86 270 bottom
EC5205  SC6D8P50V2DN-GP  [C402H22]  30.12 86.56 0 bottom
EC5206  SC6D8P50V2DN-GP  [C402H22]  30.13 84.87 180 bottom
EC5210  SC33P50V2JN-3GP  [C402H22]  18.11 89.73 270 bottom
EC6103  SC220P50V2KX-3GP  [C402H22]  178.76 18.1 180 top
EC6104  SCD1U25V2KX-GP  [C402H22]  100.31 130.84 90 top
EC6105  SC220P50V2KX-3GP  [C402H22]  178.76 16.43 0 top
EC6201  SC33P50V2JN-3GP  [C402H22]  133.64 76.1 270 top
EC6202  SC33P50V2JN-3GP  [C402H22]  135.42 76.1 90 top
EC6203  SC33P50V2JN-3GP  [C402H22]  127.75 97.88 0 bottom
EC6204  SC33P50V2JN-3GP  [C402H22]  127.75 96.16 180 bottom
EC6205  SC33P50V2JN-3GP  [C402H22]  132.89 95.67 180 bottom
EC6206  SC33P50V2JN-3GP  [C402H22]  135.05 96.87 270 bottom
EC9701  SCD1U25V2KX-GP  [C402H22]  132.09 136.91 180 top
EC9702  SCD1U25V2KX-GP  [C402H22]  150.5 60.46 180 top
EC9703  SCD1U25V2KX-GP  [C402H22]  99.7 11.17 180 top
EC9704  SCD1U25V2KX-GP  [C402H22]  140.66 35.12 270 top
EC9705  SCD1U25V2KX-GP  [C402H22]  111.2 124.4 180 bottom
EC9706  SCD1U25V2KX-GP  [C402H22]  87.5 129.56 0 top
EC9707  SCD1U25V2KX-GP  [C402H22]  55.09 89.27 270 top
EC9708  SC1KP50V2KX-1GP  [C402H22]  108.2 2.88 0 top
